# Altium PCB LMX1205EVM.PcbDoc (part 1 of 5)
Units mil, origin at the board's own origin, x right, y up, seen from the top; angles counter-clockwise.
Board outline 5000 x 5000 mil, 6 copper layers (Top Layer, RF GND, Signal Layer 3, Signal Layer 4, Signal Layer 5, Bottom Layer), stack 61.6 mil thick; 176 components, 99 nets, 572 pads, 2473 vias.
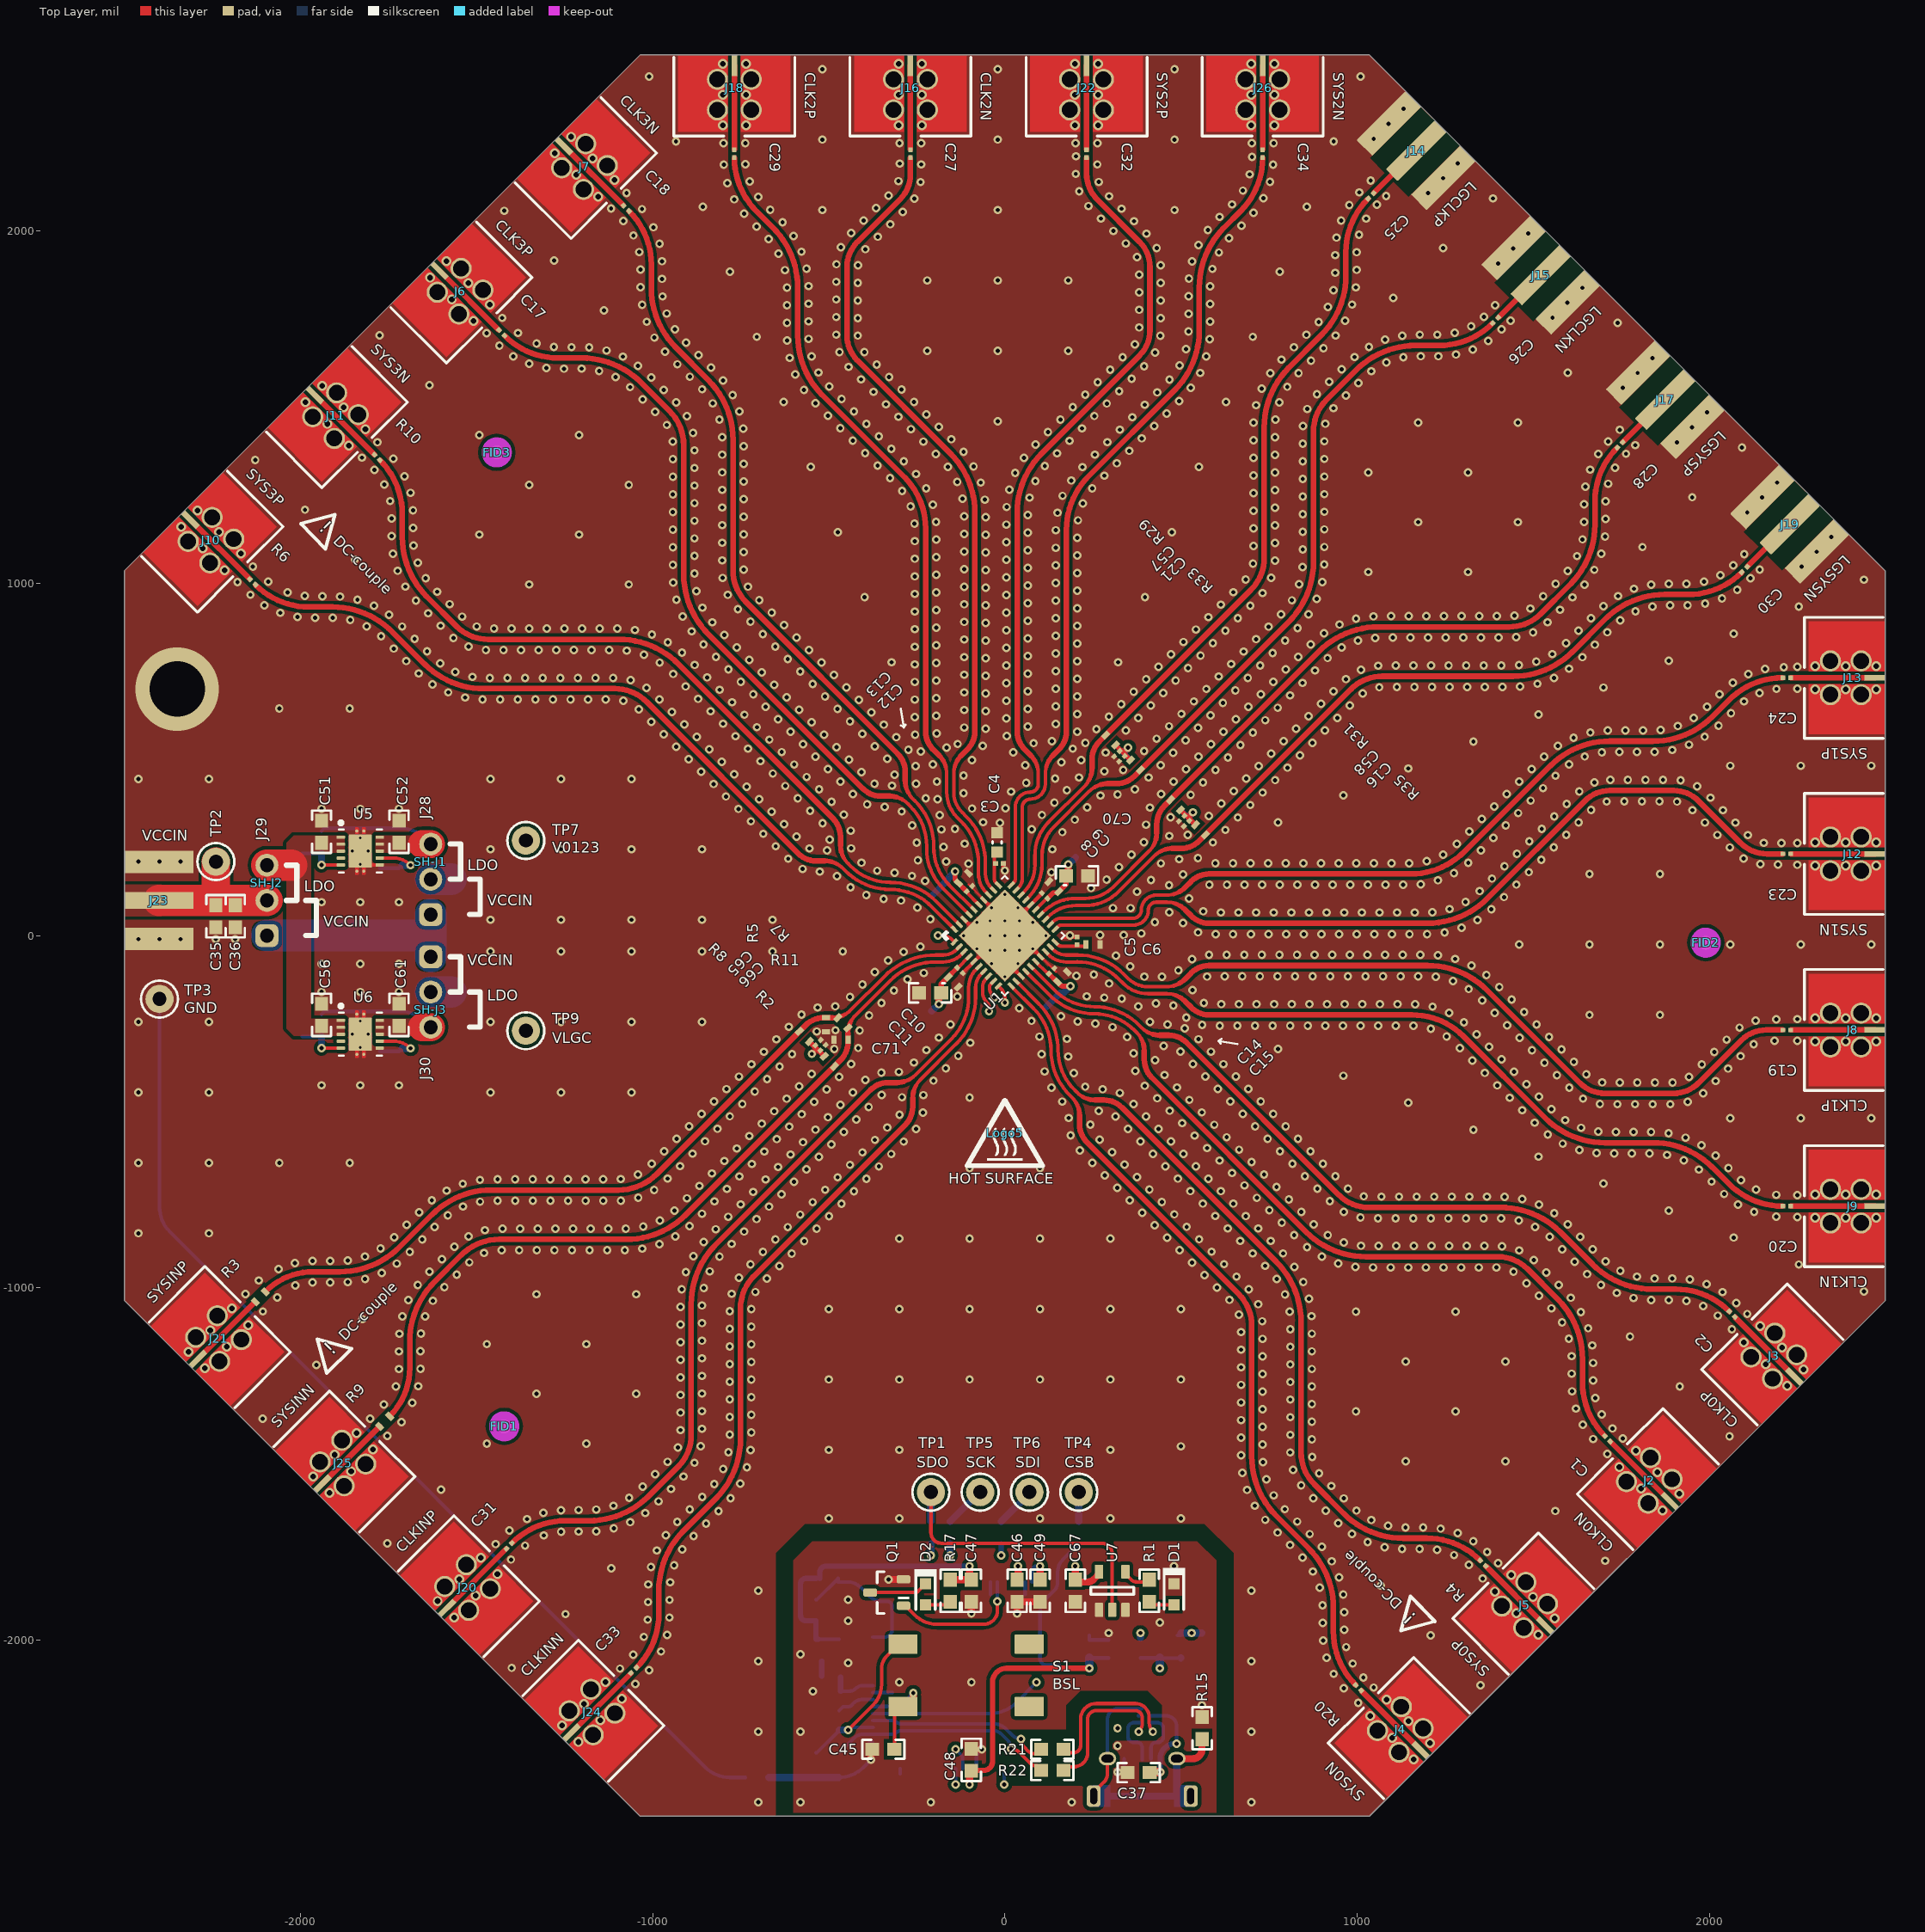
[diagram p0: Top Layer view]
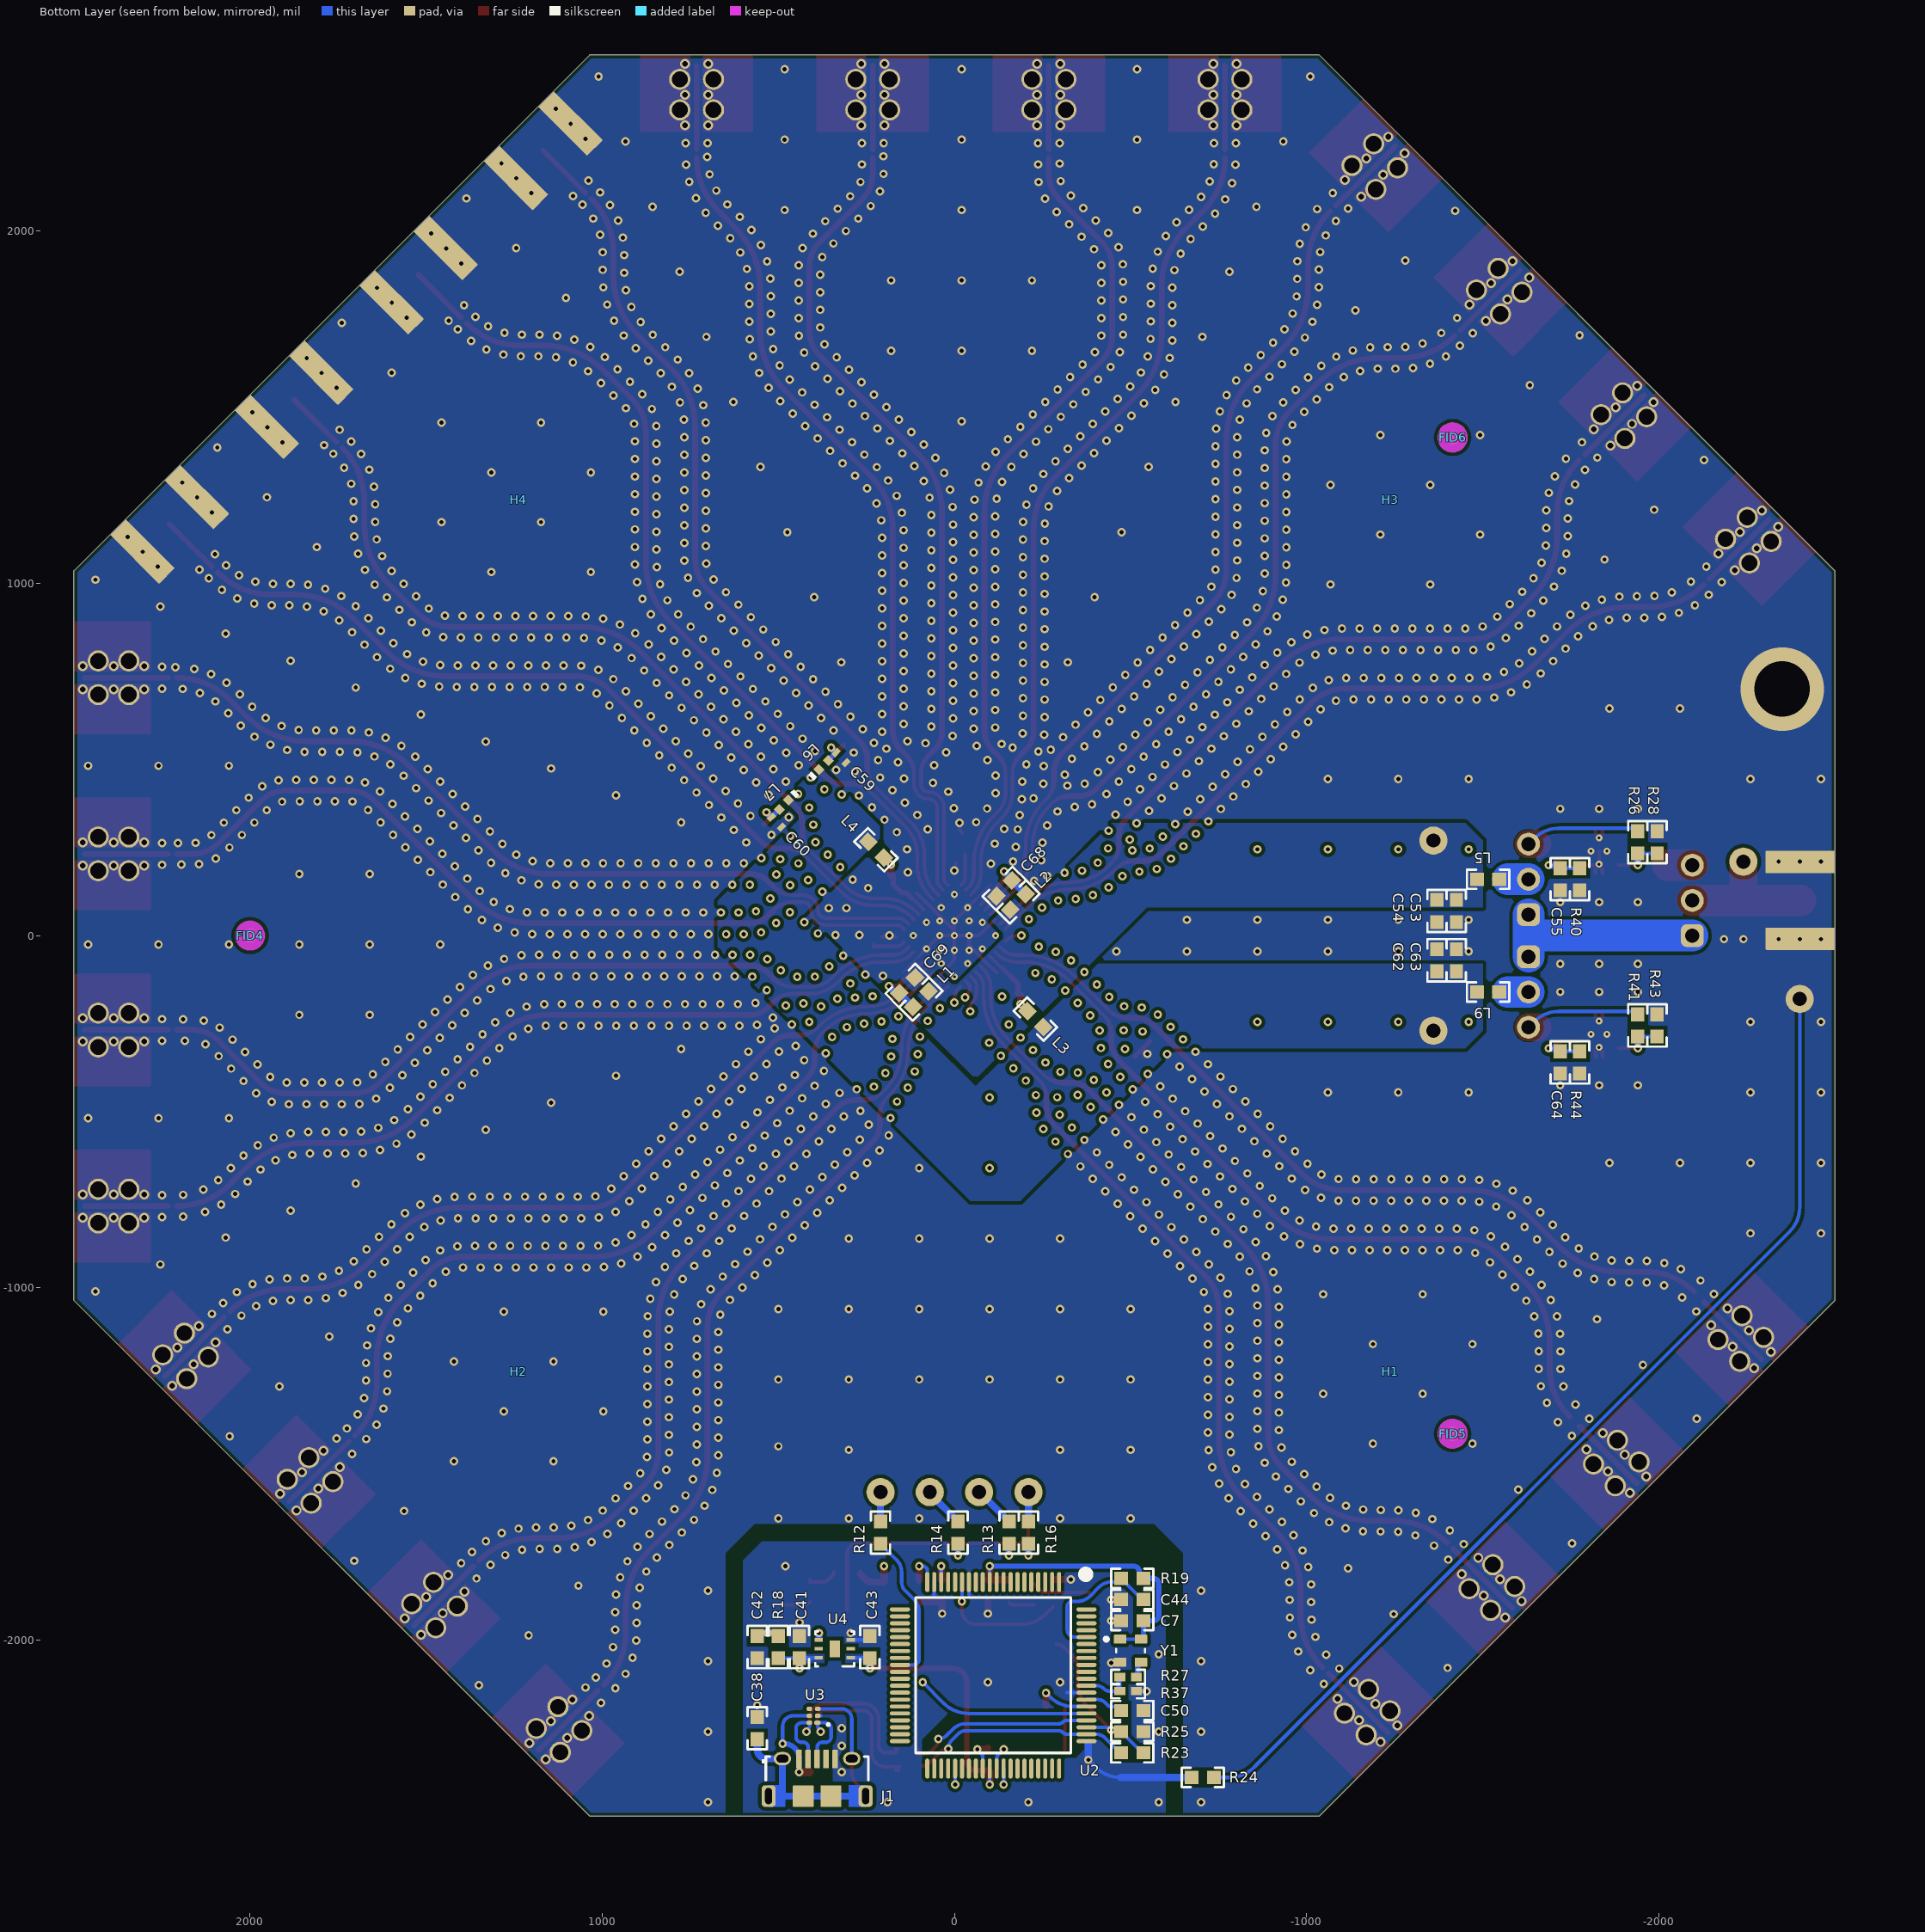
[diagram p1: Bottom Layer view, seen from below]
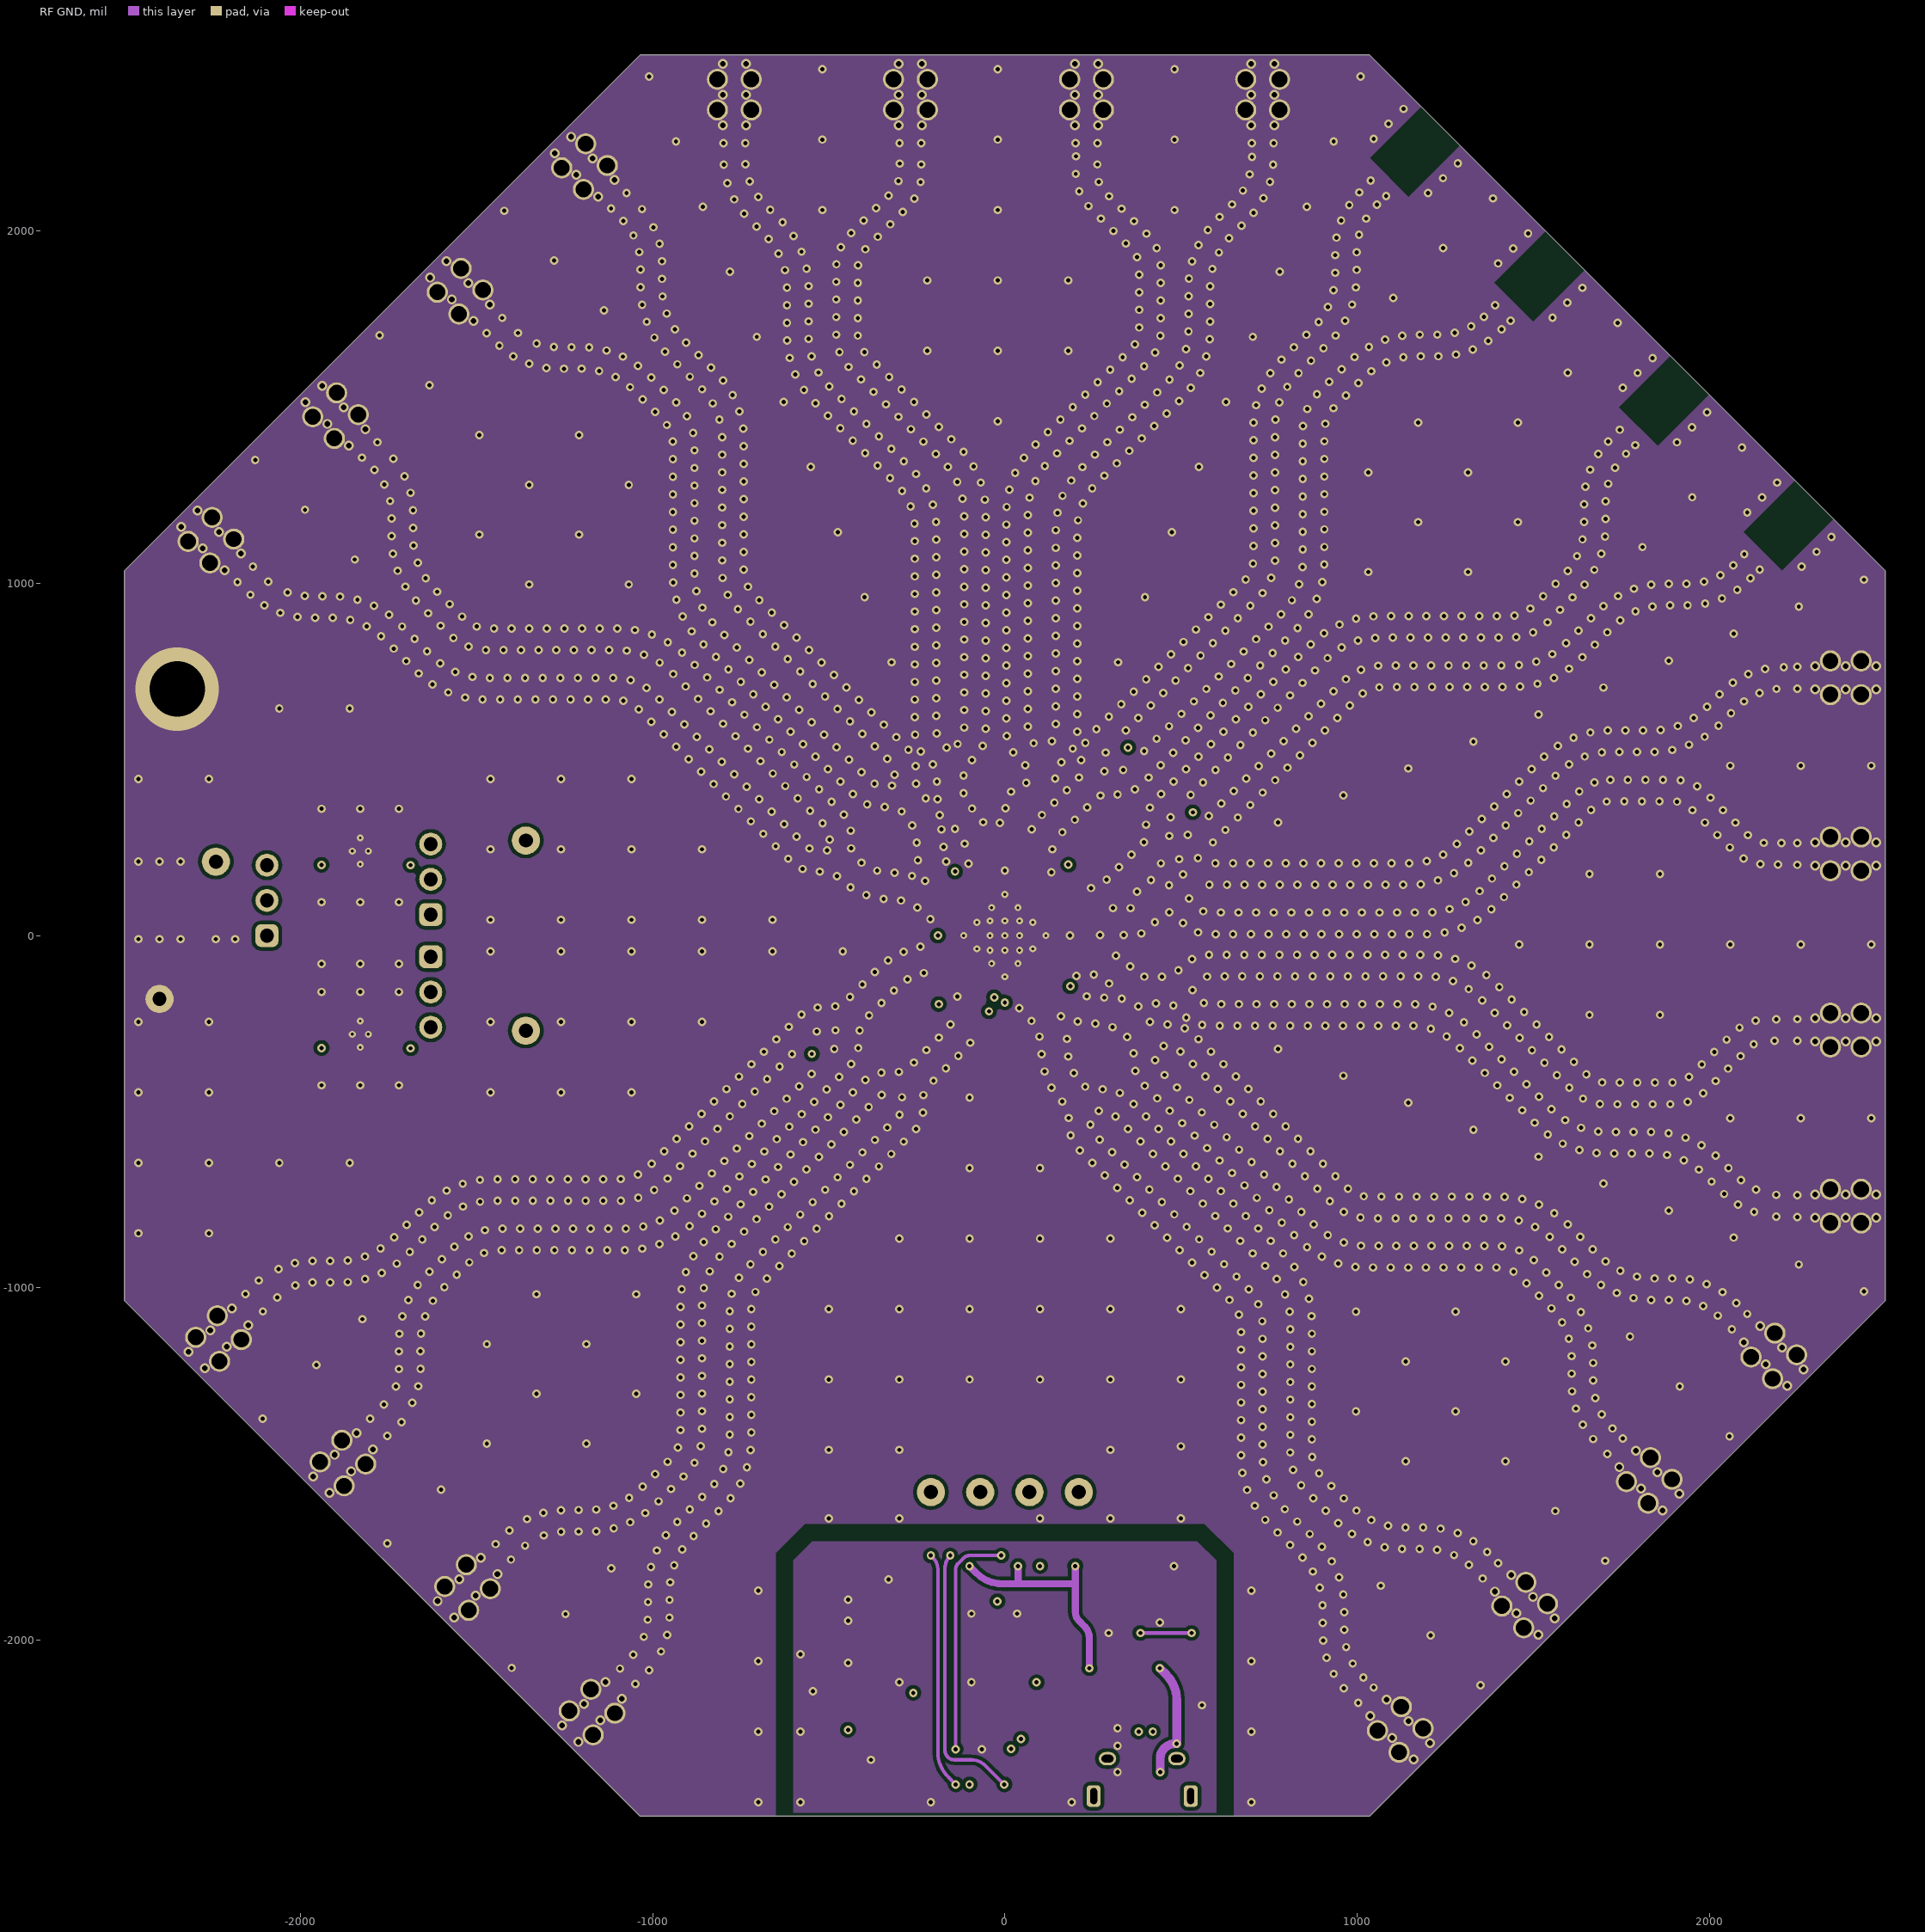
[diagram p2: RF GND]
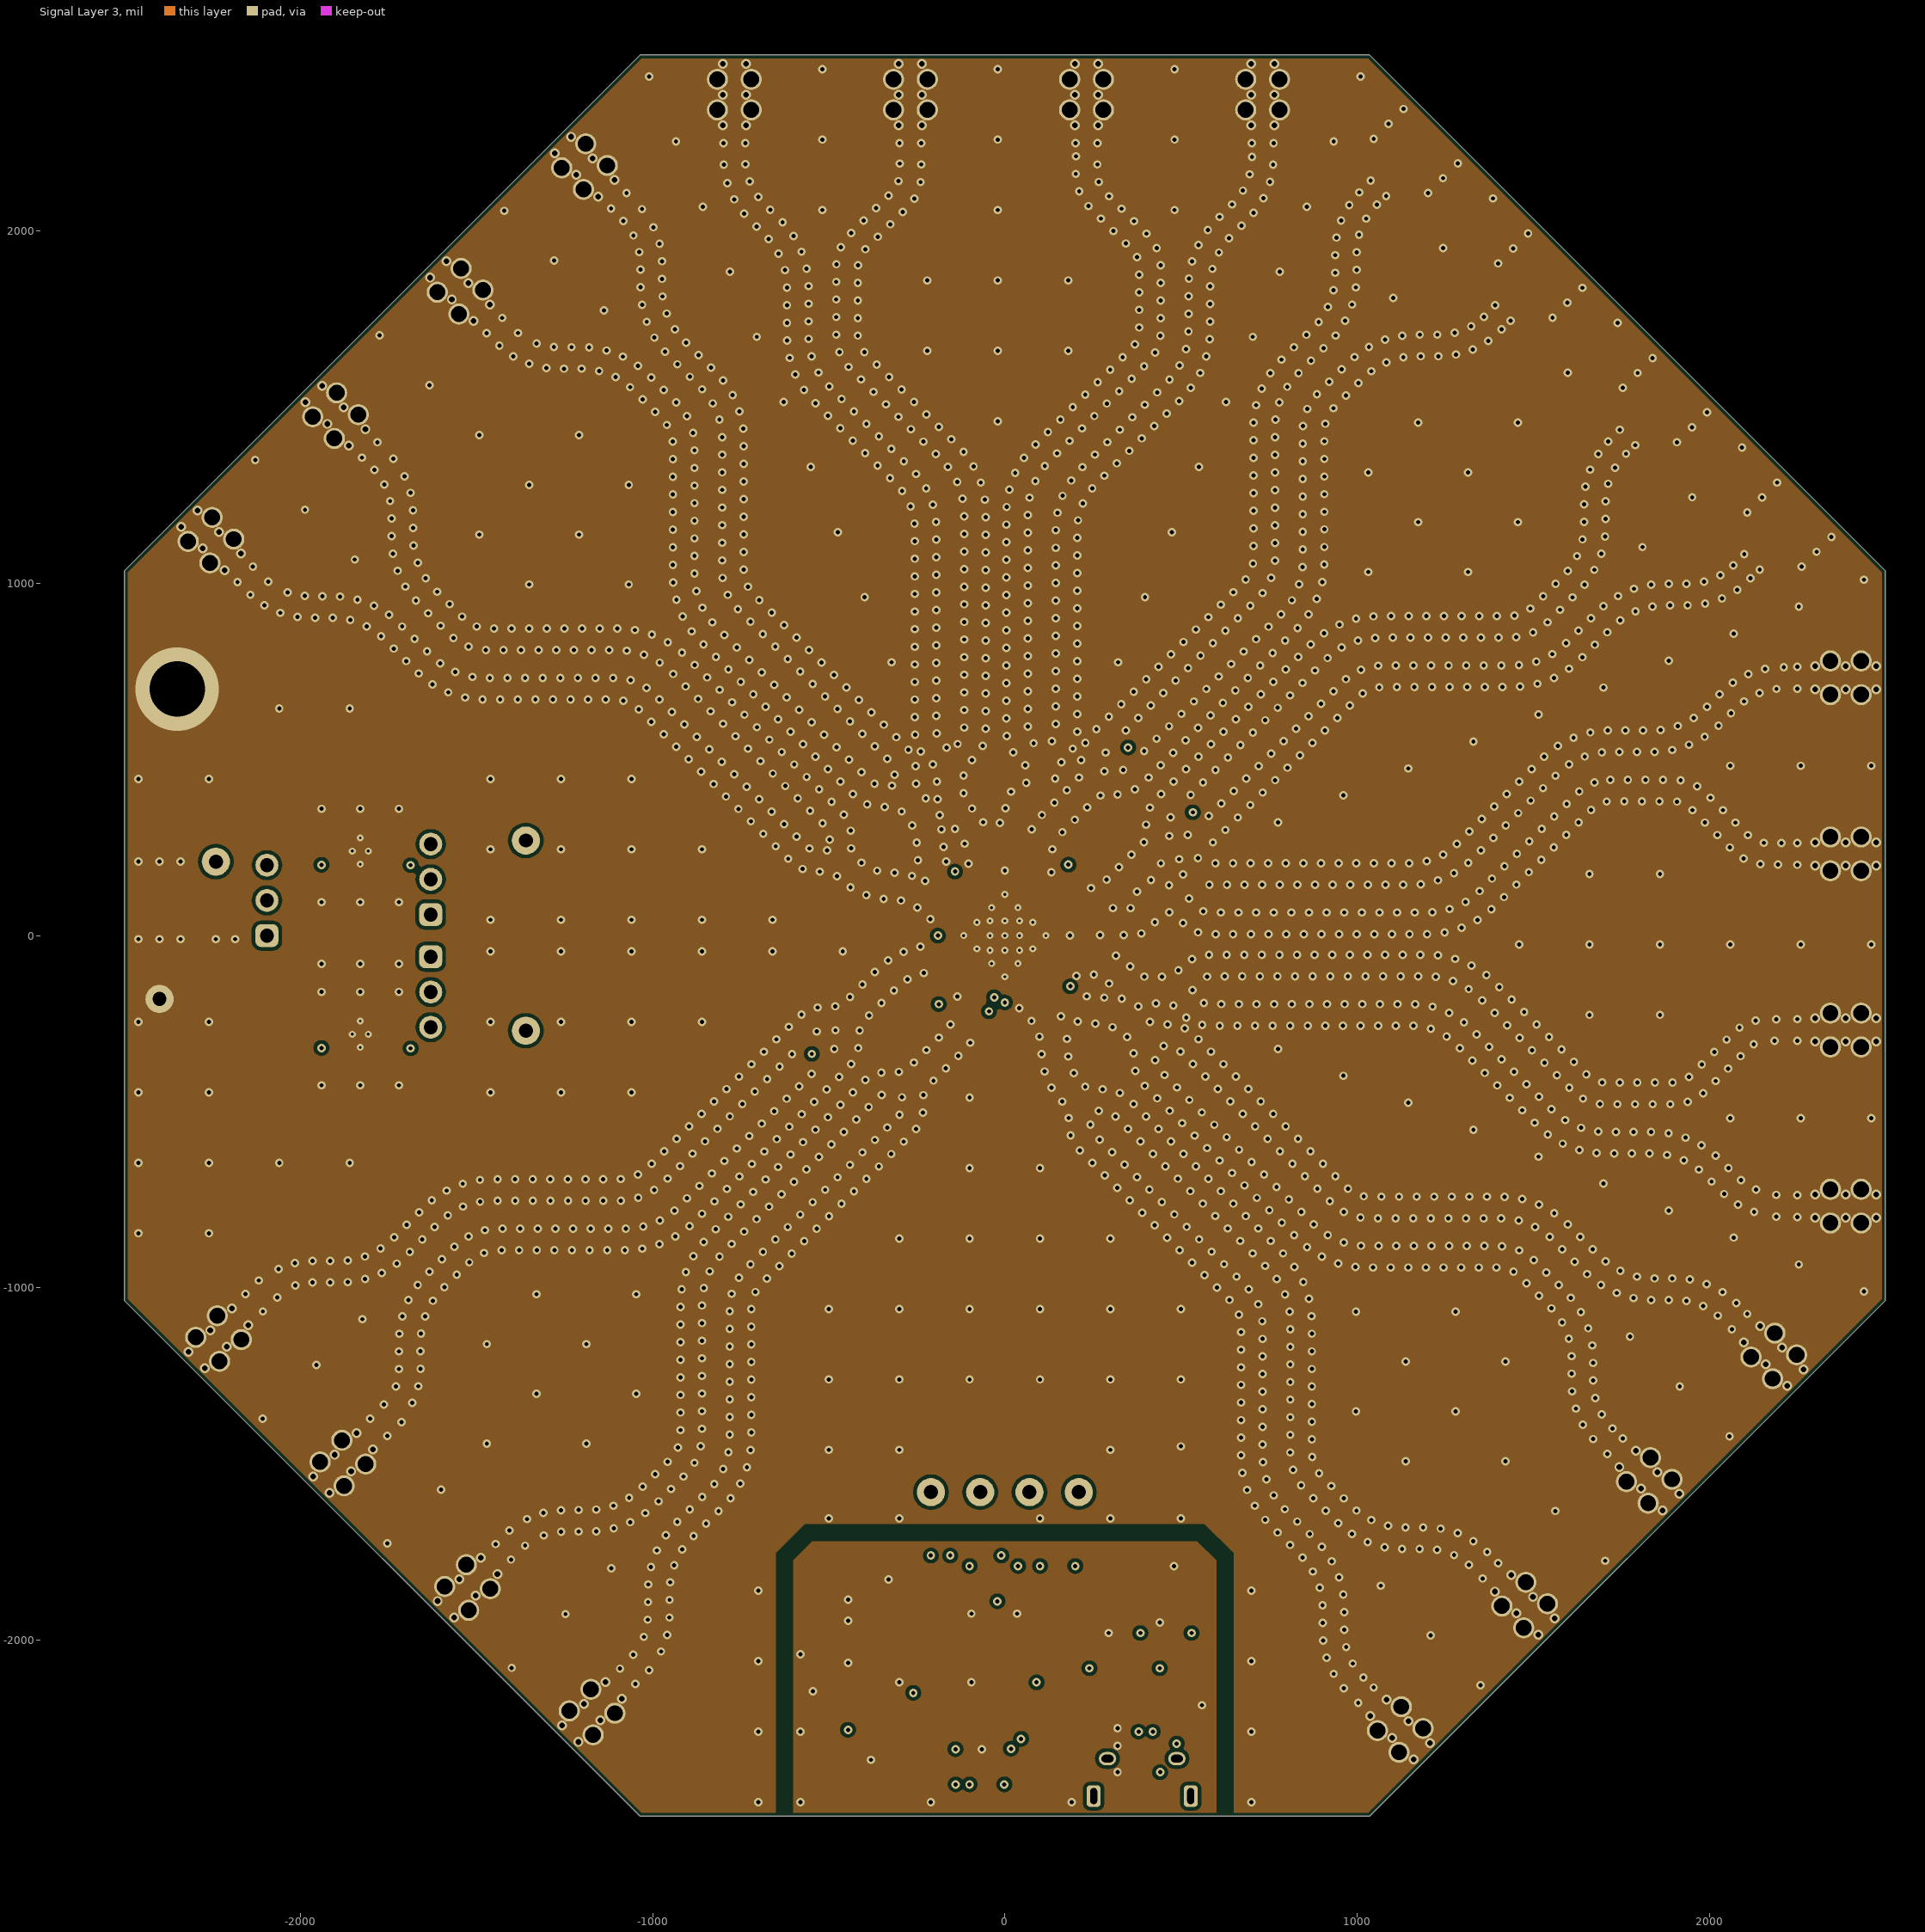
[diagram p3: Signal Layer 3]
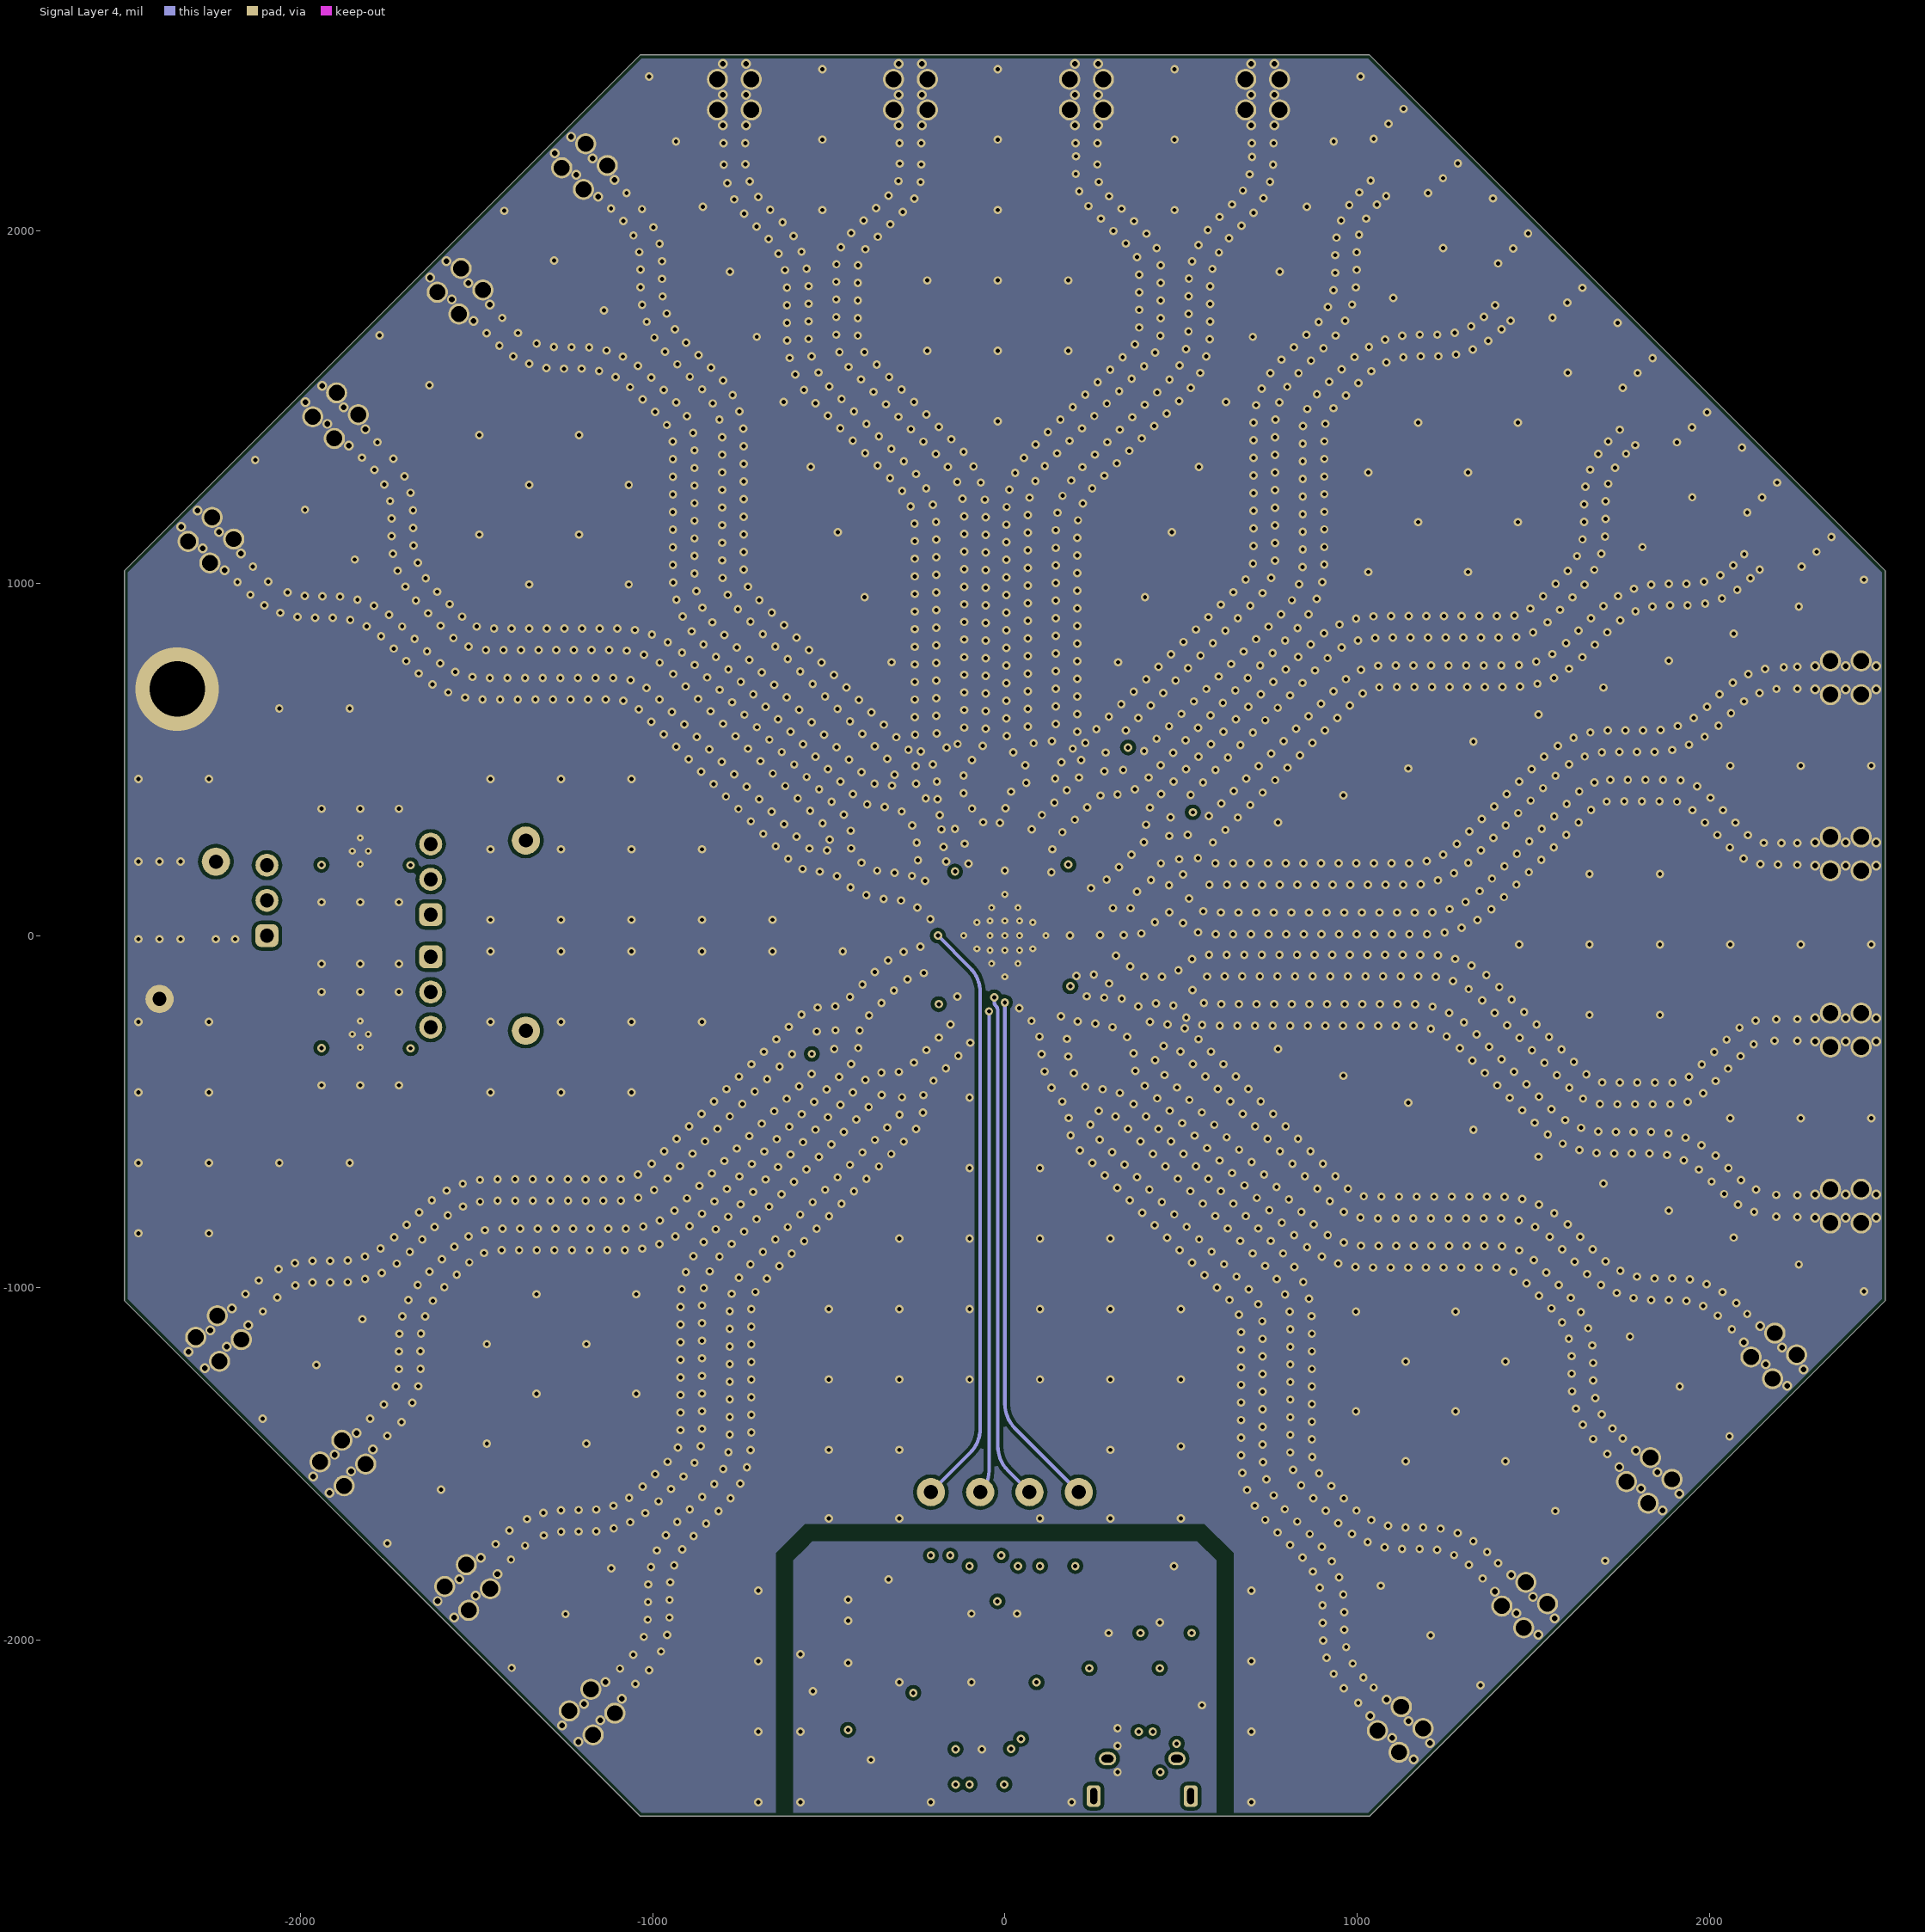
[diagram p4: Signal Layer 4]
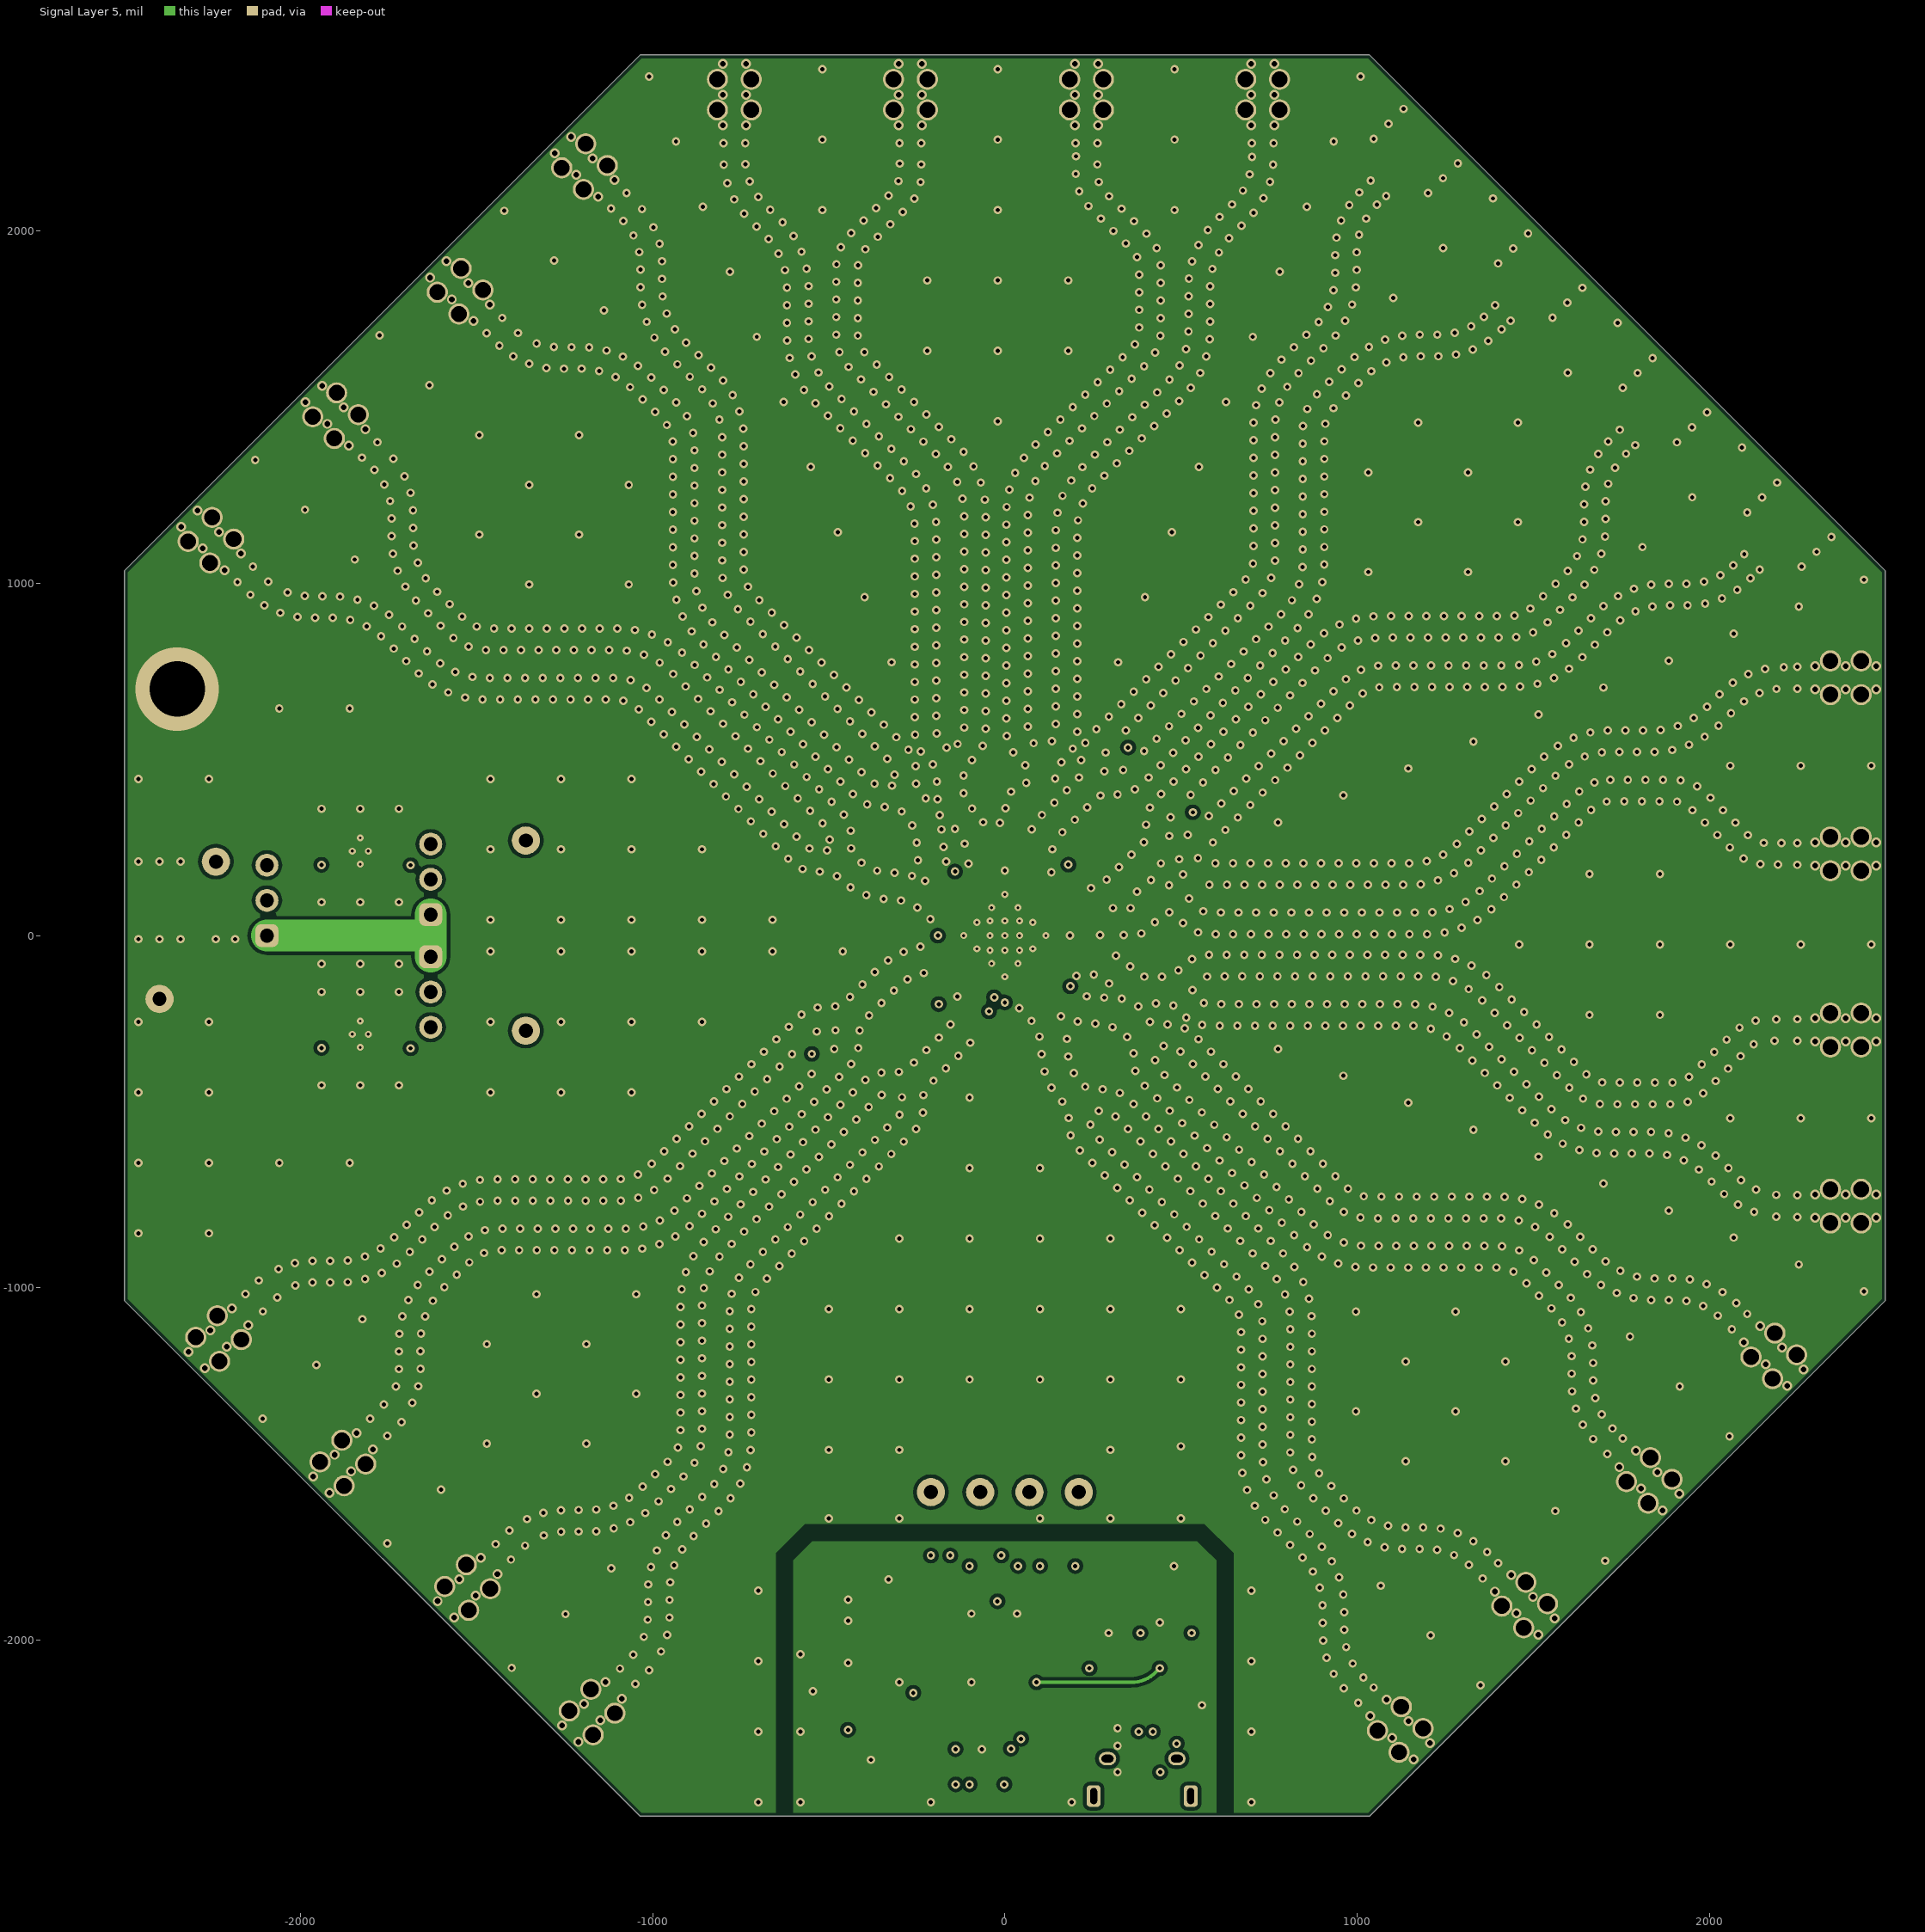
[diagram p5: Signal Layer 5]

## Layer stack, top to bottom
Top Solder: solder mask 0.4, Solder Resist, Dk 3.5
Top Layer: signal copper 2.8
Dielectric1: prepreg 8, RO4350B, Dk 3.48
RF GND: signal copper 1.4
Dielectric 2: prepreg 11, FR-4 High Tg, Dk 4.2
Signal Layer 3: signal copper 1.4
Dielectric 3: core 12.4, FR-4 High Tg, Dk 4.2
Signal Layer 4: signal copper 1.4
Dielectric 4: prepreg 11, FR-4 High Tg, Dk 4.2
Signal Layer 5: signal copper 1.4
Dielectric 5: prepreg 8, FR-4 High Tg, Dk 4.2
Bottom Layer: signal copper 2.8
Bottom Solder: solder mask 0.4, Solder Resist, Dk 3.5

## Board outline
-1035.53,-2500 -2500,-1035.53 -2500,1035.53 -1035.53,2500 1035.53,2500 2500,1035.53 2500,-1035.53 1035.53,-2500

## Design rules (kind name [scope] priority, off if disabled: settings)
AcuteAngle [All] p1: minimum=4.50000000000000E+0001 checktracksonly=FALSE
AssemblyTestPointUsage [All] p1: valid=2
BoardOutlineClearance BoardOutlineClearance_MountingHoles [OnCopper and InComponentClass('Mounting Holes')] p1: gap=10 ignorepadtopadclearanceinfootprint=FALSE
BoardOutlineClearance BoardOutlineClearance_Poly [OnCopper and IsPoly and not OnTopLayer and not OnLayer('RF GND')] p2: gap=10 ignorepadtopadclearanceinfootprint=FALSE
BoardOutlineClearance [OnCopper and Not InComponentClass('Logo') and not InComponentClass('FiducialMark') and not InRegion(1000,500,4000,800) and not InPoly and not InComponent('J1')and not InComponent('J2')and not InComponent('J3')and not InComponent('J4')and not InComponent('J5')and not InComponent('J6')and not InComponent('J7')and not InComponent('J8')and not InComponent('J9')and not InComponent('J10')and not InComponent('J11')and not InComponent('J12')and not InComponent('J13')and not InComponent('J14')and not InComponent('J15')and not InComponent('J16')and not InComponent('J17')and not InComponent('J18')and not InComponent('J19')and not InComponent('J20')and not InComponent('J21')and not InComponent('J22')and not InComponent('J23')and not InComponent('J24')and not InComponent('J25')and not InComponent('J26')and not InNet('GND')and not InNet('NetC35_1')] p3: gap=10 ignorepadtopadclearanceinfootprint=FALSE
Clearance Clearance_Keepouts [((IsTrack or IsArc) and not InPoly) and IsFree and IsKeepOut vs ((IsTrack or IsArc) and not InPoly) and IsFree and IsKeepOut] p1: gap=0 ignorepadtopadclearanceinfootprint=FALSE
Clearance IMPEDANCE [InPolygon vs InNetClass('50OHM_IMPED')] p2 off: gap=7.87 ignorepadtopadclearanceinfootprint=TRUE except(9.64: Arc-Fill Arc-Poly Arc-Region Track-Fill Track-Poly Track-Region)
Clearance Clearance_Poly [InPolygon] p3: gap=10 ignorepadtopadclearanceinfootprint=TRUE except(9.64: Arc-Fill Arc-Poly Arc-Region Track-Fill Track-Poly Track-Region)
Clearance Clearance_FiducialMark [IsKeepOut and InComponentClass('FiducialMark') vs IsPad and InComponentClass('FiducialMark')] p4: gap=0 ignorepadtopadclearanceinfootprint=TRUE
Clearance [All] p5: gap=7.87 ignorepadtopadclearanceinfootprint=TRUE
ComponentClearance ComponentClearance_MountingHoles_FiducialMarks [InComponentClass('Mounting Holes') vs InComponentClass('FiducialMark')] p1: gap=50 collisioncheckmode=3 verticalgap=10 showdistances=FALSE
ComponentClearance ComponentClearance_Shunt [InComponentClass('Header') vs InComponentClass('Shunt')] p2: gap=0 collisioncheckmode=3 verticalgap=0 showdistances=FALSE
ComponentClearance ComponentClearance_Logo [InComponentClass('Logo')] p3: gap=50 collisioncheckmode=3 verticalgap=10 showdistances=FALSE
ComponentClearance ComponentClearance_ScrewToNut [(HasFootprint('NY PMS 440 0025 PH')) vs (HasFootprint('Keystone_1902C'))] p4: gap=5 collisioncheckmode=3 verticalgap=10 showdistances=FALSE
ComponentClearance ComponentClearance_MountingHoles [InComponentClass('Mounting Holes')] p5: gap=250 collisioncheckmode=3 verticalgap=100000 showdistances=FALSE
ComponentClearance ComponentClearance_SmallPassives [HasFootprint('0201*') or HasFootprint('0402*') or HasFootprint('0508') or HasFootprint('0603*') or HasFootprint('0612') or HasFootprint('0805*') or HasFootprint('0815*') or HasFootprint('0830*') or HasFootprint('1206*') or HasFootprint('1210*') or HasFootprint('1808*') or HasFootprint('1812*') or HasFootprint('1825*') or HasFootprint('2010*') or HasFootprint('2220*') or HasFootprint('2225*') or HasFootprint('2512*') or HasFootprint('2728*') or HasFootprint('3518*') vs HasFootprint('0201*') or HasFootprint('0402*') or HasFootprint('0508') or HasFootprint('0603*') or HasFootprint('0612') or HasFootprint('0805*') or HasFootprint('0815*') or HasFootprint('0830*') or HasFootprint('1206*') or HasFootprint('1210*') or HasFootprint('1808*') or HasFootprint('1812*') or HasFootprint('1825*') or HasFootprint('2010*') or HasFootprint('2220*') or HasFootprint('2225*') or HasFootprint('2512*') or HasFootprint('2728*') or HasFootprint('3518*')] p6: gap=14.96 collisioncheckmode=3 verticalgap=10 showdistances=FALSE
ComponentClearance ComponentClearance_THtoSMT [IsThruComponent vs IsSMTComponent] p7: gap=40 collisioncheckmode=3 verticalgap=30 showdistances=FALSE
ComponentClearance ComponentClearance_THtoTH [IsThruComponent vs IsThruComponent] p8: gap=30 collisioncheckmode=3 verticalgap=30 showdistances=FALSE
ComponentClearance [All] p9: gap=30 collisioncheckmode=3 verticalgap=10 showdistances=FALSE
DiffPairsRouting [All] p1: maxlimit=100 minlimit=10 mostfreqgap=10 toplayer_minwidth=15 toplayer_maxwidth=15 toplayer_prefwidth=15 midlayer1_minwidth=15 midlayer1_maxwidth=15 midlayer1_prefwidth=15 midlayer2_minwidth=15 midlayer2_maxwidth=15 midlayer2_prefwidth=15 midlayer3_minwidth=15 midlayer3_maxwidth=15 midlayer3_prefwidth=15 midlayer4_minwidth=15 midlayer4_maxwidth=15 midlayer4_prefwidth=15 bottomlayer_minwidth=15 bottomlayer_maxwidth=15 bottomlayer_prefwidth=15 maxuncoupledlength=1000
FabricationTestPointUsage TestPointUsage [All] p1: valid=2 allowmultiple=FALSE
FabricationTestpoint Testpoint [All] p1: side=3 testpointundercomponent=TRUE minsize=40 maxsize=100 preferedsize=60 minholesize=0 maxholesize=40 preferedholesize=32 testpointgrid=1 allowsidetop=TRUE allowsidebottom=TRUE usegrid=TRUE gridtolerance=0.01
FanoutControl Fanout_LCC [IsLCC] p1: bgadir=Out bgaviamode=Centered fanoutstyle=Auto fanoutdirection=Alternating viagrid=1 // Fanout_LCC (Default Rule)
FanoutControl Fanout_BGA [IsBGA] p2: bgadir=Out bgaviamode=Centered fanoutstyle=Auto fanoutdirection=Alternating viagrid=1 // Fanout_BGA (Default Rule)
FanoutControl Fanout_Default [All] p4: bgadir=Out bgaviamode=Centered fanoutstyle=Auto fanoutdirection=Alternating viagrid=1 // Fanout_Default (Default Rule)
FanoutControl Fanout_Small [(CompPinCount < 5)] p5: bgadir=Out bgaviamode=Centered fanoutstyle=Auto fanoutdirection=OutThenIn viagrid=1 // Fanout_Small (Default Rule)
HoleSize [All] p1: absolutevalues=TRUE maxlimit=251 minlimit=7.87 maxpercent=80.000 minpercent=20.000
MinimumAnnularRing MinimumAnnularRing_ThermalPadVias [IsVia and InAnyComponent] p1: minimumring=5.91
MinimumAnnularRing [All] p2: minimumring=3
MinimumSolderMaskSliver MinimumSolderMaskSliver_Logo [InComponentClass('Logo') vs InComponentClass('Logo')] p1: minsoldermaskwidth=0.7
MinimumSolderMaskSliver [All] p2: minsoldermaskwidth=3.9
PlaneConnect [All] p1: planeconnectstyle=Relief reliefexpansion=10 reliefentries=4 reliefconductorwidth=10 reliefairgap=10
PolygonConnect [All] p1: connectstyle=Direct reliefconductorwidth=10 reliefentries=4 polygonreliefangle="90 Angle" airgapwidth=10
RoutingVias ThermalPadVias [IsVia and InAnyComponent] p1: holewidth=7.87 width=19.68 viastyle="Through Hole" minholewidth=7.87 minwidth=18 maxholewidth=16 maxwidth=28
RoutingVias AdditionalThermalVias [InNet('GND')] p2: holewidth=7.87 width=19.68 viastyle="Through Hole" minholewidth=7.87 minwidth=18 maxholewidth=160 maxwidth=240
RoutingVias [All] p3: holewidth=12 width=24 viastyle="Through Hole" minholewidth=12 minwidth=24 maxholewidth=160 maxwidth=240
SilkToBoardRegionClearance [Not ((IsComment or IsDesignator) And (Hide <> 'False')) and not InRegion(1000,500,4000,800)] p1:
SilkToSilkClearance SilkToSilkClearance_Pb-FreeLogo [(HasFootprint('Pb-Free_Overlay_Medium') OR HasFootprint('Pb-Free_Overlay_Small')) vs (HasFootprint('Pb-Free_Overlay_Medium') OR HasFootprint('Pb-Free_Overlay_Small'))] p1: silktosilkclearance=0
SilkToSilkClearance [All] p2: silktosilkclearance=3.94
SilkToSolderMaskClearance SilkToComponentPadClearance [(IsPad or IsFill or IsRegion) and InAnycomponent] p1: minsilkscreentomaskgap=5 clearancetoexposedcopper=TRUE
SilkToSolderMaskClearance "Silk to Solder Mask Opening" [All] p2: minsilkscreentomaskgap=3.94 clearancetoexposedcopper=FALSE
SolderMaskExpansion [All] p1: expansion=1.97
UnRoutedNet [All] p1: checkbadconnections=TRUE
Width [All] p1: maxlimit=100 minlimit=6 preferedwidth=10 checkconnectedcopper=TRUE
14 further rules are at their usual default settings.

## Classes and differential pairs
component class Shunt: SH-J1 SH-J2 SH-J3
net class 50OHM_IMPED: C2N C2P LGCN LGCP LGSN LGSP NetC1_1 NetC1_2 NetC2_1 NetC2_2 NetC17_1 NetC17_2 NetC18_1 NetC18_2 NetC19_1 NetC19_2 NetC20_1 NetC20_2 NetC23_1 NetC23_2 NetC24_1 NetC24_2 NetC25_1 NetC26_1 NetC27_1 NetC28_1 NetC29_1 NetC30_1 NetC31_1 NetC31_2 NetC32_1 NetC33_1 NetC33_2 NetC34_1 NetJ4_1 NetJ5_1 NetJ10_1 NetJ11_1 NetJ21_1 NetJ25_1 NetR2_1 NetR3_2 NetR4_2 NetR6_1 NetR10_1 NetR20_2 S2N S2P
component class LMX1205EVM_USB2ANY: C7 C37 C38 C41 C42 C43 C44 C45 C46 C47 C48 C49 C50 C67 D1 D2 J1 Q1 R1 R12 R13 R14 R15 R16 R17 R18 R19 R21 R22 R23 R24 R25 R27 R37 S1 TP1 TP4 TP5 TP6 U2 U3 U4 U7 Y1
component class LMX1205EVM_PWR: C35 C36 C51 C52 C53 C54 C55 C56 C61 C62 C63 C64 J23 J28 J29 J30 L5 L9 R26 R28 R40 R41 R43 R44 SH-J1 SH-J2 SH-J3 TP2 TP3 TP7 TP9 U5 U6
component class LMX1205EVM_BUF: C1 C2 C3 C4 C5 C6 C8 C9 C10 C11 C12 C13 C14 C15 C16 C17 C18 C19 C20 C21 C23 C24 C25 C26 C27 C28 C29 C30 C31 C32 C33 C34 C57 C58 C59 C60 C65 C66 C68 C69 C70 C71 J2 J3 J4 J5 J6 J7 J8 J9 J10 J11 J12 J13 J14 J15 J16 J17 J18 J19 J20 J21 J22 J24 J25 J26 L1 L2 L3 L4 L6 L7 R2 R3 R4 R5 R6 R7 R8 R9 R10 R11 R20 R29 R31 R33 R35 U1
component class Header: J28 J29 J30
component class LMX1205EVM_Hardware: FID1 FID2 FID3 FID4 FID5 FID6 H1 H2 H3 H4 Logo5
component class FiducialMark: FID1 FID2 FID3 FID4 FID5 FID6

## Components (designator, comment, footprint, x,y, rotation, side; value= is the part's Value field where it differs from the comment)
C1 "ATC530Z104KT10T" 0201_033L 1711.2,-1428.36 r135 top value=0.1uF
C2 "ATC530Z104KT10T" 0201_033L 2064.75,-1074.8 r135 top value=0.1uF
C3 "ATC530Z104KT10T" 0201_033L -15,205 r0 top value=0.1uF
C4 "GRM188R61A106KAALD" 0603L -22,265 r90 top value=10uF
C5 "550Z103PTT" 0201_033L 205,-15 r90 top value=0.01uF
C6 "GRM155R61E105KA12D" 0402S 250,-25 r0 top value=1uF
C7 "885012206046" 0603 -505,-1945 r0 bottom value=0.1uF
C8 "ATC530Z104KT10T" 0201_033L 113.14,113.14 r135 top value=0.1uF
C9 "GRM155R61E105KA12D" 0402S 139.3,139.3 r135 top value=1uF
C10 "ATC530Z104KT10T" 0201_033L -127.28,-98.99 r315 top value=0.1uF
C11 "GRM155R61E105KA12D" 0402S -146.72,-131.88 r315 top value=1uF
C12 "ATC530Z104KT10T" 0201_033L -100.41,132.94 r45 top value=0.1uF
C13 "GRM155R61E105KA12D" 0402S -117.73,163.7 r45 top value=1uF
C14 "ATC530Z104KT10T" 0201_033L 132.94,-100.41 r45 top value=0.1uF
C15 "GRM155R61E105KA12D" 0402S 163.7,-117.73 r45 top value=1uF
C16 "ATC530Z104KT10T" 0201_033L 516.19,318.2 r45 top value=0.1uF
C17 "ATC530Z104KT10T" 0201_033L -1428.36,1711.2 r135 top value=0.1uF
C18 "ATC530Z104KT10T" 0201_033L -1074.8,2064.75 r135 top value=0.1uF
C19 "ATC530Z104KT10T" 0201_033L 2220,-268 r180 top value=0.1uF
C20 "ATC530Z104KT10T" 0201_033L 2220,-768 r180 top value=0.1uF
C21 "ATC530Z104KT10T" 0201_033L 332.34,502.05 r45 top value=0.1uF
C23 "ATC530Z104KT10T" 0201_033L 2220,232 r180 top value=0.1uF
C24 "ATC530Z104KT10T" 0201_033L 2220,732 r180 top value=0.1uF
C25 "ATC530Z104KT10T" 0201_033L 1039.45,2100.11 r225 top value=0.1uF
C26 "ATC530Z104KT10T" 0201_033L 1393,1746.55 r225 top value=0.1uF
C27 "ATC530Z104KT10T" 0201_033L -268,2220 r270 top value=0.1uF
C28 "ATC530Z104KT10T" 0201_033L 1746.55,1393 r225 top value=0.1uF
C29 "ATC530Z104KT10T" 0201_033L -768,2220 r270 top value=0.1uF
C30 "ATC530Z104KT10T" 0201_033L 2100.11,1039.45 r225 top value=0.1uF
C31 "ATC530Z104KT10T" 0201_033L -1407.14,-1732.41 r45 top value=0.1uF
C32 "ATC530Z104KT10T" 0201_033L 232,2220 r270 top value=0.1uF
C33 "ATC530Z104KT10T" 0201_033L -1053.59,-2085.96 r45 top value=0.1uF
C34 "ATC530Z104KT10T" 0201_033L 732,2220 r270 top value=0.1uF
C35 "885012206052" 0603 -2240,55 r270 top value=1uF
C36 "885012206046" 0603 -2185,55 r270 top value=0.1uF
C37 "885012106018" 0603 380,-2376 r180 top value=2.2uF
C38 "885012206086" 0603 560,-2250 r90 bottom value=3300pF
C41 "885012206052" 0603 440,-2020 r90 bottom value=1uF
C42 "885012206046" 0603 560,-2020 r270 bottom value=0.1uF
C43 "885012206052" 0603 240,-2020 r90 bottom value=1uF
C44 "885012206036" 0603 -505,-1885 r0 bottom value=2200pF
C45 "C0603C221J5GACTU" 0603 -345,-2310 r180 top value=220pF
C46 "885012206046" 0603 35,-1860 r270 top value=0.1uF
C47 "885012206046" 0603 -95,-1860 r270 top value=0.1uF
C48 "885012206046" 0603 -95,-2340 r90 top value=0.1uF
C49 "GRM188R71C474KA88D" 0603 100,-1860 r270 top value=0.47uF
C50 "C0603C221J5GACTU" 0603 -505,-2200 r180 bottom value=220pF
C51 "GRM188R61A106KAALD" 0603 -1940,295 r90 top value=10uF
C52 "GRM188R61A106KAALD" 0603 -1720,295 r90 top value=10uF
C53 "GRM188R61A106KAALD" 0603 -1425,70 r90 bottom value=10uF
C54 "885012206046" 0603 -1370,70 r270 bottom value=0.1uF
C55 "GRM188Z71C475KE21D" 0603 -1720,160 r270 bottom value=4.7uF
C56 "GRM188R61A106KAALD" 0603 -1940,-225 r90 top value=10uF
C57 "ATC530Z104KT10T" 0201_033L 318.2,516.19 r45 top value=0.1uF
C58 "ATC530Z104KT10T" 0201_033L 502.05,332.34 r45 top value=0.1uF
C59 "GRM155R61E105KA12D" 0402S 321.73,505.58 r225 bottom value=1uF
C60 "GRM155R61E105KA12D" 0402S 505.58,321.73 r225 bottom value=1uF
C61 "GRM188R61A106KAALD" 0603 -1720,-225 r90 top value=10uF
C62 "GRM188R61A106KAALD" 0603 -1370,-70 r270 bottom value=10uF
C63 "885012206046" 0603 -1425,-70 r90 bottom value=0.1uF
C64 "GRM188Z71C475KE21D" 0603 -1720,-360 r270 bottom value=4.7uF
C65 "ATC530Z104KT10T" 0201_033L -530.33,-304.06 r225 top value=0.1uF
C66 "ATC530Z104KT10T" 0201_033L -516.19,-318.2 r225 top value=0.1uF
C67 "885012206046" 0603 200,-1860 r270 top value=0.1uF
C68 "GRM188R61A106KAALD" 0603 -141.42,134.35 r135 bottom value=10uF
C69 "GRM188R61A106KAALD" 0603 134.35,-141.42 r315 bottom value=10uF
C70 "GRM188R61A106KAALD" 0603 205.06,169.71 r180 top value=10uF
C71 "GRM188R61A106KAALD" 0603 -212.13,-162.63 r0 top value=10uF
D1 "LD" LED_LTST-C190 480,-1870 r90 top value=Green
D2 "USB" LED_LTST-C190 -225,-1870 r90 top value=Green
FID1 "Fiducial" Fiducial10-20 -1421.28,-1393 r0 top
FID2 "Fiducial" Fiducial10-20 1990,-20 r0 top
FID3 "Fiducial" Fiducial10-20 -1442.5,1371.79 r0 top
FID4 "Fiducial" Fiducial10-20 2000,0 r180 bottom
FID5 "Fiducial" Fiducial10-20 -1414.21,-1414.21 r225 bottom
FID6 "Fiducial" Fiducial10-20 -1414.21,1414.21 r180 bottom
H1 "SJ61A6" 3M_SJ61A6 -1237.44,-1237.44 r180 bottom
H2 "SJ61A6" 3M_SJ61A6 1237.44,-1237.44 r180 bottom
H3 "SJ61A6" 3M_SJ61A6 -1237.44,1237.44 r180 bottom
H4 "SJ61A6" 3M_SJ61A6 1237.44,1237.44 r180 bottom
J1 "10118194-0001LF" FCI_10118194-0001LF 390,-2500 r180 bottom
J2 "CLK0N" Johnson_142-0761-881 1829.64,-1546.8 r225 top
J3 "CLK0P" Johnson_142-0761-881 2183.19,-1193.24 r225 top
J4 "SYS0N" Johnson_142-0761-881 1122.53,-2253.9 r225 top
J5 "SYS0P" Johnson_142-0761-881 1476.09,-1900.35 r225 top
J6 "CLK3P" Johnson_142-0761-881 -1546.8,1829.64 r45 top
J7 "CLK3N" Johnson_142-0761-881 -1193.24,2183.19 r45 top
J8 "CLK1P" Johnson_142-0761-881 2387.5,-268 r270 top
J9 "CLK1N" Johnson_142-0761-881 2387.5,-768 r270 top
J10 "SYS3P" Johnson_142-0761-881 -2253.9,1122.53 r45 top
J11 "SYS3N" Johnson_142-0761-881 -1900.35,1476.09 r45 top
J12 "SYS1N" Johnson_142-0761-881 2387.5,232 r270 top
J13 "SYS1P" Johnson_142-0761-881 2387.5,732 r270 top
J14 "LGCLKP" FP-CON-SMA-EDGE-S_CONN_JACK-MFG 1370.02,2430.68 r315 top
J15 "LGCLKN" FP-CON-SMA-EDGE-S_CONN_JACK-MFG 1723.57,2077.13 r315 top
J16 "CLK2N" Johnson_142-0761-881 -268,2387.5 r0 top
J17 "LGSYSP" FP-CON-SMA-EDGE-S_CONN_JACK-MFG 2077.13,1723.57 r315 top
J18 "CLK2P" Johnson_142-0761-881 -768,2387.5 r0 top
J19 "LGSYSN" FP-CON-SMA-EDGE-S_CONN_JACK-MFG 2430.68,1370.02 r315 top
J20 "CLKINP" Johnson_142-0761-881 -1525.58,-1850.85 r135 top
J21 "SYSINP" Johnson_142-0761-881 -2232.69,-1143.75 r135 top
J22 "SYS2P" Johnson_142-0761-881 232,2387.5 r0 top
J23 "VCCIN" FP-CON-SMA-EDGE-S_CONN_JACK-MFG -2687.5,100 r90 top
J24 "CLKINN" Johnson_142-0761-881 -1172.03,-2204.41 r135 top
J25 "SYSINN" Johnson_142-0761-881 -1879.14,-1497.3 r135 top
J26 "SYS2N" Johnson_142-0761-881 732,2387.5 r0 top
J28 "TSW-103-07-G-S" TSW-103-07-G-S -1630,160 r90 top
J29 "TSW-103-07-G-S" TSW-103-07-G-S -2095,100 r90 top
J30 "TSW-103-07-G-S" TSW-103-07-G-S -1630,-160 r270 top
L1 "120Ω" 0603 95.46,-180.31 r315 bottom value="120 ohm"
L2 "120Ω" 0603 -180.31,95.46 r135 bottom value="120 ohm"
L3 "120Ω" 0603 -229.81,-236.88 r45 bottom value="120 ohm"
L4 "120Ω" 0603 222.74,243.95 r225 bottom value="120 ohm"
L5 "120Ω" 0603 -1515,160 r0 bottom value="120 ohm"
L6 "LQG15HS18NJ02D" IND_LQG15H 371.23,484.37 r135 bottom value=18nH
L7 "LQG15HS18NJ02D" IND_LQG15H 484.37,371.23 r315 bottom value=18nH
L9 "120Ω" 0603 -1515,-160 r0 bottom value="120 ohm"
Logo5 "HOT SURFACE" IEC_HotSurface_Small 0,-560 r0 top
Q1 "BSS138" SOT-23 -335,-1865 r180 top value=50V
R1 "CRCW0603330RJNEA" 0603 410,-1860 r90 top value=330
R2 "CRCW040210K0JNED" 0402S -498.51,-357.09 r135 top value=10k
R3 "CRCW04020000Z0ED" 0402S -2114.25,-1025.3 r45 top value=0
R4 "CRCW02010000Z0ED" 0201L 1357.65,-1781.91 r135 top value=0
R5 "CRCW040210K0JNED" 0402S -507.7,-253.14 r90 top value=10k
R6 "CRCW02010000Z0ED" 0201L -2135.46,1004.09 r135 top value=0
R7 "CRCW0402100RJNED" 0402S -459.62,-247.49 r135 top value=100
R8 "CRCW040210K0JNED" 0402S -569.22,-286.38 r315 top value=10k
R9 "CRCW04020000Z0ED" 0402S -1760.7,-1378.86 r45 top value=0
R10 "CRCW02010000Z0ED" 0201L -1781.91,1357.65 r135 top value=0
R11 "CRCW040210K0JNED" 0402S -465.28,-295.57 r0 top value=10k
R12 "CRCW0603200RFKEA" 0603 210,-1695 r90 bottom value=200
R13 "CRCW0603200RFKEA" 0603 -155,-1695 r90 bottom value=200
R14 "CRCW0603200RFKEA" 0603 -10,-1695 r90 bottom value=200
R15 "CRCW06031M00JNEA" 0603 560,-2250 r270 top value=1.0Meg
R16 "CRCW0603200RFKEA" 0603 -210,-1695 r90 bottom value=200
R17 "CRCW0603330RJNEA" 0603 -155,-1860 r90 top value=330
R18 "CRCW060310K0JNEA" 0603 500,-2020 r270 bottom value=10k
R19 "CRCW060333K0JNEA" 0603 -505,-1825 r180 bottom value=33k
R20 "CRCW02010000Z0ED" 0201L 1004.09,-2135.46 r135 top value=0
R21 "CRCW060333R0JNEA" 0603 135,-2310 r180 top value=33
R22 "CRCW060333R0JNEA" 0603 135,-2370 r180 top value=33
R23 "CRCW06031K50JNEA" 0603 -505,-2320 r0 bottom value=1.5k
R24 "CRCW06030000Z0EA" 0603 -705,-2390 r180 bottom value=0
R25 "CRCW06031M20JNEA" 0603 -505,-2260 r0 bottom value=1.2Meg
R26 "CRCW0603133KFKEA" 0603 -1940,265 r90 bottom value=133k
R27 "CRCW04021K78FKED" 0402 -493,-2105 r0 bottom value=1.78k
R28 "CRCW060312K4FKEA" 0603 -1995,265 r270 bottom value=12.4k
R29 "CRCW040249R9FKED" 0402S 300.52,555.08 r135 top value=49.9
R31 "CRCW040249R9FKED" 0402S 484.37,371.23 r135 top value=49.9
R33 "CRCW040249R9FKED" 0402S 371.23,484.37 r135 top value=49.9
R35 "CRCW040249R9FKED" 0402S 555.08,300.52 r135 top value=49.9
R37 "CRCW04021K00FKED" 0402 -493,-2145 r0 bottom value=1.00k
R40 "CRCW060316K5FKEA" 0603 -1775,160 r90 bottom value=16.5k
R41 "CRCW0603133KFKEA" 0603 -1940,-255 r90 bottom value=133k
R43 "CRCW060312K4FKEA" 0603 -1994.93,-255 r270 bottom value=12.4k
R44 "CRCW060316K5FKEA" 0603 -1775,-360 r90 bottom value=16.5k
S1 "BSL" SW_FSM4JSMA -110,-2100 r90 top
SH-J1 "SNT-100-BK-G" SNT-100-BK-G -1630,210 r270 top value=1x2
SH-J2 "SNT-100-BK-G" SNT-100-BK-G -2095,150 r270 top value=1x2
SH-J3 "SNT-100-BK-G" SNT-100-BK-G -1630,-210 r270 top value=1x2
TP1 "SDO" Keystone5002 -210,-1580 r90 top
TP2 "VCCIN" Keystone5000 -2240,210 r0 top
TP3 "GND" Keystone5001 -2400,-180 r90 top
TP4 "CSB" Keystone5002 210,-1580 r90 top
TP5 "SCK" Keystone5002 -70,-1580 r90 top
TP6 "SDI" Keystone5002 70,-1580 r90 top
TP7 "V0123" Keystone5000 -1360,270 r90 top
TP9 "VLGC" Keystone5000 -1360,-270 r90 top
U1 "LMX1205" RHA0040C-MFG 0,0 r45 top
U2 "MSP430F5529IPN" PN0080A_N -110,-2100 r270 bottom
U3 "TPD4S009DRYR" DRY0006A 400,-2215 r0 bottom
U4 "LP5900SDX-3.3/NOPB" NGF0006A 340,-2025 r0 bottom
U5 "TPS7A9401DSC" DSC0010J-MFG -1830,240 r0 top
U6 "TPS7A9401DSC" DSC0010J-MFG -1830,-280 r0 top
U7 "SN74LVC1G17DBVR" DBV0005A_N 305,-1860 r90 top
Y1 "CDC6CXXXXXXXDLFT" DLF0004A-MFG -500,-2030 r180 bottom

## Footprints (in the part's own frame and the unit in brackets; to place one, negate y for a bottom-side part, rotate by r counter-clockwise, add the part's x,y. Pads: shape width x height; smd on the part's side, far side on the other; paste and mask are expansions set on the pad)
3M_SJ61A6 [mil] "BUMPER CYLIN 0.312\" DIA"
  body extent -156,-156 156,156, height 195
0201_033L [mm] "0201"
  rect 0.36x0.32 smd mask+0.048: 1(-0.28,0) 2(0.28,0)
  body extent -0.31,-0.16 0.31,0.16, height 0.33
0201L [mm] "Data from Kemet datasheet CC101_COM dated 7/28/11"
  rect 0.36x0.32 smd mask+0.048: 1(-0.28,0) 2(0.28,0)
  body extent -0.31,-0.16 0.31,0.16, height 0.26
0402 [mm] "0402 from SM-752 data"
  rect 0.8x0.6 smd: 1(-0.6,0) 2(0.6,0)
  silkscreen extent -1.22,-0.52 1.22,0.52, body extent -0.55,-0.3 0.55,0.3, height 0.6
0402S [mil] "Based on C0402S footprint from PADS legacy"
  rect 15x24 smd: 1(-20,0) 2(20,0)
  body extent -22,-12 22,12, height 24
0603 [mm] "0603 from SM-752 data"
  rect 1x0.95 smd: 1(-0.8,0) 2(0.8,0)
  silkscreen extent -1.52,-0.69 1.52,0.69, body extent -0.87,-0.47 0.87,0.47, height 1
0603L [mm] "0603 from SM-752 data"
  rect 0.8x0.85 smd: 1(-0.7,0) 2(0.7,0)
  silkscreen extent -0.07,-0.33 0.07,0.32, body extent -0.87,-0.47 0.87,0.47, height 1
DBV0005A_N [mm] "SOT23, 5-Leads, Body 2.9x1.6mm, Pitch 0.95mm, Lead Span 2.8mm, IPC Medium Density"
  rrect17% 1x0.6 smd: 1(-1.375,0.95) 2(-1.375,0) 3(-1.375,-0.95) 4(1.375,-0.95) 5(1.375,0.95)
  silkscreen extent -0.25,-1.55 0.25,1.55, body extent -1.42,-1.46 1.42,1.46, height 1.09
DLF0004A-MFG [mm]
  rrect15% 0.9x0.65 smd paste-1000 mask+0: 1(-0.75,0.825) 2(-0.75,-0.825) 3(0.75,-0.825) 4(0.75,0.825)
  silkscreen extent -1.88,-0.13 1.05,0.95, body extent -1,-1.25 1,1.25, height 1
DRY0006A [mm] "USON-6"
  rrect67% 0.45x0.3 smd paste-0.05 mask-0.05: 1(-0.275,0.5)
  rrect67% 0.4x0.3 smd paste-0.05 mask-0.05: 2(-0.3,0) 3(-0.3,-0.5) 4(0.3,-0.5) 5(0.3,0) 6(0.3,0.5)
  body extent -0.5,-0.72 0.5,0.72, height 0.58
DSC0010J-MFG [mm]
  rrect42% 0.6x0.24 smd paste+0 mask+0: 1(-1.4,1) 2(-1.4,0.5) 3(-1.4,0) 4(-1.4,-0.5) 5(-1.4,-1) 6(1.4,-1) 7(1.4,-0.5) 8(1.4,0) 9(1.4,0.5) 10(1.4,1)
  round 0.225 smd paste-1000 mask+0: 11(-0.25,-1.45) 11(-0.25,1.448) 11(0.25,1.45) 11(0.25,-1.448)
  rrect6% 1.65x2.4 smd paste-1000 mask+0: 11(0,0)
  Top Layer region: 0.375,-1.2 0.375,-1.65 0.371,-1.669 0.36,-1.685 0.344,-1.696 0.325,-1.7 0.325,-1.7 0.175,-1.7 0.156,-1.696 0.14,-1.685 0.129,-1.669 0.125,-1.65 0.125,-1.65 0.125,-1.2
  Top Layer region: -0.125,-1.2 -0.125,-1.65 -0.132,-1.675 -0.15,-1.693 -0.175,-1.7 -0.175,-1.7 -0.325,-1.7 -0.344,-1.696 -0.36,-1.685 -0.371,-1.669 -0.375,-1.65 -0.375,-1.65 -0.375,-1.2
  Top Layer region: 0.125,1.2 0.125,1.65 0.129,1.669 0.14,1.685 0.156,1.696 0.175,1.7 0.175,1.7 0.325,1.7 0.344,1.696 0.36,1.685 0.371,1.669 0.375,1.65 0.375,1.65 0.375,1.2
  Top Layer region: -0.375,1.2 -0.375,1.65 -0.371,1.669 -0.36,1.685 -0.344,1.696 -0.325,1.7 -0.325,1.7 -0.175,1.7 -0.156,1.696 -0.14,1.685 -0.129,1.669 -0.125,1.65 -0.125,1.65 -0.125,1.2
  silkscreen extent -1.55,-1.55 1.55,2.16, body extent -1.8,-1.8 1.8,1.8, height 0.25
FCI_10118194-0001LF [mm] "USB-micro B USB 2.0, 0.65mm, 5 Pos, R/A, SMT"
  rrect25% 0.4x1.35 smd: 1(-1.3,4.125) 2(-0.65,4.125) 3(0,4.125) 4(0.65,4.125) 5(1.3,4.125)
  rrect100% 1.25x0.95 hole 0.55 slot 0.85 at 0 deg mask+0.064: 6(-2.5,4.15) 7(2.5,4.15)
  rrect50% 1.008x1.55 hole 0.5 slot 1.15 at 90 deg: 8(-3.5,1.45) 9(3.5,1.45)
  rrect7% 1.5x1.55 smd: 10(-1,1.45) 11(1,1.45)
  Top Layer region: -3.445,0.675 -3.544,0.675 -3.728,0.751 -3.869,0.892 -3.945,1.076 -3.945,1.175 -3.945,1.175 -3.945,1.175 -3.945,1.725 -3.945,1.824 -3.869,2.008 -3.728,2.149 -3.544,2.225 -3.445,2.225 -3.445,2.225 -2.3,2.225 -2.3,0.675
  Top Layer region: 3.445,0.675 3.544,0.675 3.728,0.751 3.869,0.892 3.945,1.076 3.945,1.175 3.945,1.175 3.945,1.175 3.945,1.725 3.945,1.824 3.869,2.008 3.728,2.149 3.544,2.225 3.445,2.225 3.445,2.225 2.3,2.225 2.3,0.675
  silkscreen extent -4,2.6 3.7,4.3, body extent -4.02,-1.23 4.03,4.35, height 2.72
Fiducial10-20 [mm]
  round 1 smd mask+0.5: 1(0,0)
  Top Layer keep-out circle w1.178: c0,0 r0.5
FP-CON-SMA-EDGE-S_CONN_JACK-MFG [mm]
  rrect8% 1.2x5 smd paste+0 mask+0: 1(0,-7.26)
  rrect6% 1.6x5 smd paste+0 mask+0: 2(-2.77,-7.26) 3(2.77,-7.26)
  rrect6% 1.6x5 smd far side paste+0 mask+0: 4(-2.77,-7.26) 5(2.77,-7.26)
  body extent -3.28,-9.86 3.28,4.86, height 0.25
IEC_HotSurface_Small [mil]
  silkscreen extent -107,-93 107,92
IND_LQG15H [mm] "MuRata"
  rect 0.55x0.6 smd: 1(-0.475,0) 2(0.475,0)
  silkscreen extent -1.3,-0.3 -0.95,0.3, body extent -0.52,-0.27 0.52,0.27, height 0.55
Johnson_142-0761-881 [mil] "Connector, TH, End launch SMA"
  rect 16x60 smd: 1(0,82.5)
  round 60 hole 45 mask+0: 2(-48,43.5) 3(-48,-43.5) 4(48,-43.5) 5(48,43.5)
  Top Layer region: -18.01,112.5 -160.01,112.5 -160.01,-105.5 -18.01,-105.5
  Top Layer region: 17.99,-105.49 159.99,-105.49 159.99,112.51 17.99,112.51
  silkscreen extent -172,-117 172,106, body extent -124,-67 123,497, height 128
Keystone5000 [mil] "For Keystone 500x miniature loop terminals"
  round 80 hole 40: 1(0,0)
  silkscreen extent -52,-52 52,52, body extent -49,-49 49,49, height 182
Keystone5001 [mil] "For Keystone 500x miniature loop terminals"
  round 80 hole 40: 1(0,0)
  silkscreen extent -52,-52 52,52, body extent -49,-49 49,49, height 182
Keystone5002 [mil] "For Keystone 500x miniature loop terminals"
  round 80 hole 40: 1(0,0)
  silkscreen extent -52,-52 52,52, body extent -49,-49 49,49, height 182
LED_LTST-C190 [mm] "Lite-On"
  rect 0.8x0.8 smd: 1(-0.75,0) 2(0.75,0)
  silkscreen extent -1.1,-0.8 1.89,0.8, body extent -0.85,-0.45 0.85,0.45, height 0.9
NGF0006A [mm] "TI"
  rect 0.6x0.25 smd: 1(-1.15,0.65) 2(-1.15,0) 3(-1.15,-0.65) 4(1.15,-0.65) 5(1.15,0) 6(1.15,0.65)
  rect 0.75x1.2 smd paste-0.38: 7(0,0)
  silkscreen extent -1.4,-1.25 1.4,1.25, body extent -1.3,-1.15 1.3,1.15, height 0.81
PN0080A_N [mm] "QFP, 80-Leads, Body 12x12mm, Pitch 0.5mm, IPC Medium Density"
  oval 1.45x0.3 smd: 1(-6.725,4.75) 2(-6.725,4.25) 3(-6.725,3.75) 4(-6.725,3.25) 5(-6.725,2.75) 6(-6.725,2.25) 7(-6.725,1.75) 8(-6.725,1.25) 9(-6.725,0.75) 10(-6.725,0.25) 11(-6.725,-0.25) 12(-6.725,-0.75) 13(-6.725,-1.25) 14(-6.725,-1.75) 15(-6.725,-2.25) 16(-6.725,-2.75) 17(-6.725,-3.25) 18(-6.725,-3.75) 19(-6.725,-4.25) 20(-6.725,-4.75) 41(6.725,-4.75) 42(6.725,-4.25) 43(6.725,-3.75) 44(6.725,-3.25) 45(6.725,-2.75) 46(6.725,-2.25) 47(6.725,-1.75) 48(6.725,-1.25) 49(6.725,-0.75) 50(6.725,-0.25) 51(6.725,0.25) 52(6.725,0.75) 53(6.725,1.25) 54(6.725,1.75) 55(6.725,2.25) 56(6.725,2.75) 57(6.725,3.25) 58(6.725,3.75) 59(6.725,4.25) 60(6.725,4.75)
  oval 0.3x1.45 smd: 21(-4.75,-6.725) 22(-4.25,-6.725) 23(-3.75,-6.725) 24(-3.25,-6.725) 25(-2.75,-6.725) 26(-2.25,-6.725) 27(-1.75,-6.725) 28(-1.25,-6.725) 29(-0.75,-6.725) 30(-0.25,-6.725) 31(0.25,-6.725) 32(0.75,-6.725) 33(1.25,-6.725) 34(1.75,-6.725) 35(2.25,-6.725) 36(2.75,-6.725) 37(3.25,-6.725) 38(3.75,-6.725) 39(4.25,-6.725) 40(4.75,-6.725) 61(4.75,6.725) 62(4.25,6.725) 63(3.75,6.725) 64(3.25,6.725) 65(2.75,6.725) 66(2.25,6.725) 67(1.75,6.725) 68(1.25,6.725) 69(0.75,6.725) 70(0.25,6.725) 71(-0.25,6.725) 72(-0.75,6.725) 73(-1.25,6.725) 74(-1.75,6.725) 75(-2.25,6.725) 76(-2.75,6.725) 77(-3.25,6.725) 78(-3.75,6.725) 79(-4.25,6.725) 80(-4.75,6.725)
  silkscreen extent -7.53,-5.6 5.6,6.92, body extent -7,-7 7,7, height 1.56
RHA0040C-MFG [mm]
  rrect40% 0.6x0.25 smd paste+0 mask+0: 1(-2.9,2.25) 2(-2.9,1.75) 3(-2.9,1.25) 4(-2.9,0.75) 5(-2.9,0.25) 6(-2.9,-0.25) 7(-2.9,-0.75) 8(-2.9,-1.25) 9(-2.9,-1.75) 10(-2.9,-2.25) 21(2.9,-2.25) 22(2.9,-1.75) 23(2.9,-1.25) 24(2.9,-0.75) 25(2.9,-0.25) 26(2.9,0.25) 27(2.9,0.75) 28(2.9,1.25) 29(2.9,1.75) 30(2.9,2.25)
  rrect40% 0.25x0.6 smd paste+0 mask+0: 11(-2.25,-2.9) 12(-1.75,-2.9) 13(-1.25,-2.9) 14(-0.75,-2.9) 15(-0.25,-2.9) 16(0.25,-2.9) 17(0.75,-2.9) 18(1.25,-2.9) 19(1.75,-2.9) 20(2.25,-2.9) 31(2.25,2.9) 32(1.75,2.9) 33(1.25,2.9) 34(0.75,2.9) 35(0.25,2.9) 36(-0.25,2.9) 37(-0.75,2.9) 38(-1.25,2.9) 39(-1.75,2.9) 40(-2.25,2.9)
  rrect2% 4.7x4.7 smd paste-1000 mask+0: 41(0,0)
  silkscreen extent -3.05,-3.05 3.05,3.05, body extent -3.3,-3.3 3.3,3.3, height 0.25
SNT-100-BK-G [mil] "Samtec STEP model"
  round 1 on Mech3: 0(0,0)
  body extent -100,-50 100,50, height 344
SOT-23 [mm] "SOT23, 3-Leads, Body 2.9x1.3mm, Pitch 0.95mm, Lead Span 2.5mm, IPC Medium Density"
  rrect50% 1x0.6 smd: 1(-1.2,0.95) 2(-1.2,-0.95) 3(1.2,0)
  silkscreen extent -1.62,-1.5 0.7,1.5, body extent -1.16,-1.45 1.21,1.45, height 1
SW_FSM4JSMA [mm] "Alcoswitch"
  rrect7% 1.4x2.1 smd: 1(2.25,4.55) 2(2.25,-4.55) 3(-2.25,4.55) 4(-2.25,-4.55)
  body extent -3,-5 3,5, height 5.09
TSW-103-07-G-S [mm] "Samtec 100mil, 1x3, 230 mil above insulator"
  rrect50% 1.65x1.65 hole 1.016: 1(-2.54,0)
  round 1.65 hole 1.016: 2(0,0) 3(2.54,0)
  body extent -3.81,-1.27 3.81,1.27, height 8.38

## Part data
C1 C2 C3 C8 C10 C12 C14 C16 C17 C18 C19 C20 C21 C23 C24 C25 C26 C27 C28 C29 C30 C31 C32 C33 C34 C57 C58 C65 C66: library part CMP-0076713-1, "CAP, CERM, 0.1 µF, 10 V,+/- 10%, X5R, 0201", Cap_Case=0201, Manufacturer="American Technical Ceramics", PartNumber=530Z104KT10T, Supplier Part Number 1=1284-1882-1-ND, TempCo=X5R, Tolerance_%=10%, Value2=10V, ValueDisplayed=0.1µF
C4 C51 C52 C53 C56 C61 C62 C68 C69 C70 C71: library part CMP-0086193-1, "CAP, CERM, 10 µF, 10 V,+/- 10%, X5R, 0603", Cap_Case=0603, Manufacturer=MuRata, TempCo=X5R, Tolerance_%=10%, Value2=10V, ValueDisplayed=10µF
C5: library part CMP-0009631-3, "CAP, CERM, 10nF, 6.3 V, +100/-0%, C0G/NP0, 0201", Cap_Case=0201, Manufacturer="AT Ceramics", Supplier Part Number 1=1284-1002-1-ND, TempCo=C0G/NP0, Tolerance_%=100%, Value1=Unknown, Value2=6.3V, ValueDisplayed=10nF
C6 C9 C11 C13 C15 C59 C60: library part CMP-0006608-2, "CAP, CERM, 1 µF, 25 V, +/- 10%, X5R, 0402", Cap_Case=0402, Manufacturer=MuRata, Supplier Part Number 1=490-10017-1-ND, TempCo=X5R, Tolerance_%=10%, Value1=Unknown, Value2=25V, ValueDisplayed=1µF
C7 C36 C42 C46 C47 C48 C54 C63 C67: library part CMP-0006829-4, "CAP, CERM, 0.1 uF, 16 V, +/- 10%, X7R, 0603", Cap_Case=0603, Manufacturer="Wurth Elektronik", Supplier Part Number 1=710-885012206046, TempCo=X7R, Tolerance_%=10%, Value1=Unknown, Value2=16V, ValueDisplayed=0.1uF
C35 C41 C43: library part CMP-0006831-4, "CAP, CERM, 1 uF, 16 V, +/- 10%, X7R, 0603", Cap_Case=0603, Manufacturer="Wurth Elektronik", Supplier Part Number 1=710-885012206052, TempCo=X7R, Tolerance_%=10%, Value1=Unknown, Value2=16V, ValueDisplayed=1uF
C37: library part CMP-0006825-5, "CAP, CERM, 2.2 uF, 16 V, +/- 20%, X5R, 0603", Cap_Case=0603, Manufacturer="Wurth Elektronik", Supplier Part Number 1=732-7915-1-ND, TempCo=X5R, Tolerance_%=20%, Value1=Unknown, Value2=16V, ValueDisplayed=2.2uF
C38: library part CMP-0077942-1, "CAP, CERM, 3300 pF, 50 V,+/- 10%, X7R, 0603", Cap_Case=0603, Manufacturer="Wurth Elektronik", Supplier Part Number 1=732-8004-1-ND, TempCo=X7R, Tolerance_%=10%, Value2=50V, ValueDisplayed=3300pF
C44: library part CMP-0006827-4, "CAP, CERM, 2200 pF, 16 V, +/- 10%, X7R, 0603", Cap_Case=0603, Manufacturer="Wurth Elektronik", Supplier Part Number 1=710-885012206036, TempCo=X7R, Tolerance_%=10%, Value1=Unknown, Value2=16V, ValueDisplayed=2200pF
C45 C50: library part CMP-0006893-4, "CAP, CERM, 220 pF, 50 V, +/- 5%, C0G/NP0, 0603", Cap_Case=0603, Manufacturer=Kemet, Supplier Part Number 1=399-1066-1-ND, TempCo=C0G/NP0, Tolerance_%=5%, Value1=Unknown, Value2=50V, ValueDisplayed=220pF
C49: library part CMP-0007398-4, "CAP, CERM, 0.47 uF, 16 V, +/- 10%, X7R, 0603", Cap_Case=0603, Manufacturer=MuRata, Supplier Part Number 1=490-3295-1-ND, TempCo=X7R, Tolerance_%=10%, Value1=Unknown, Value2=16V, ValueDisplayed=0.47uF
C55 C64: library part CMP-0064936-4, "CAP, CERM, 4.7 uF, 16 V,+/- 10%, X7R, 0603", Cap_Case=0603, Manufacturer=MuRata, TempCo=X7R, Tolerance_%=10%, Value1=Unknown, Value2=16V, ValueDisplayed=4.7uF
D1 D2: library part CMP-0002827-3, "LED, Green, SMD", Color=green, Manufacturer=Lite-On, PartNumber=LTST-C190GKT, Power_TotalModule=100mW, Value1=0.1W, Value2=2.1V
FID1 FID2 FID3 FID4 FID5 FID6: library part CMP-0077181-1, "Fiducial mark.  There is nothing to buy or mount.", Manufacturer=N/A
H1 H2 H3 H4: library part CMP-0079645-1, "BUMPER CYLIN 0.312\" DIA", Manufacturer=3M, Supplier Part Number 1=SJ61A6-ND
J1: library part CMP-0074596-2, "Receptacle, USB 2.0, Micro-USB Type B, R/A, SMT", Color=Black, Current_A=1.8A, Manufacturer=FCI, Supplier Part Number 1=609-4618-1-ND, Voltage_V=100V
J2 J3 J4 J5 J6 J7 J8 J9 J10 J11 J12 J13 J16 J18 J20 J21 J22 J24 J25 J26: library part CMP-0055835-1, "Connector, End launch SMA 50 ohm, TH", Manufacturer="Cinch Connectivity", PartNumber=142-0761-881, Supplier Part Number 1=J801-ND
J14 J15 J17 J19 J23: library part CMP-0088000-4, "CONN SMA JACK STR EDGE MNT", Manufacturer="RF Solutions Ltd.", PartNumber=CON-SMA-EDGE-S
J28 J29 J30: library part CMP-0075407-2, "Header, 100mil, 3x1, Gold, TH", Color=Black, Current_A=6.3A, Manufacturer=Samtec, Supplier Part Number 1=SAM1029-03-ND, Voltage_V=550V
L1 L2 L3 L4 L5 L9: library part CMP-0003352-2, "Ferrite Bead, 120 ohm @ 100 MHz, 3 A, 0603", Manufacturer=MuRata, PartNumber=BLM18SG121TN1D, Supplier Part Number 1=490-3996-1-ND, Value1="0.025 ohm", Value2=3A, ValueDisplayed="120 ohm"
L6 L7: library part CMP-0058614-1, "Inductor, Multilayer, Air Core, 18 nH, 0.3 A, 0.36 ohm, SMD", Manufacturer=MuRata, Supplier Part Number 1=490-2626-1-ND, Value1="0.36 ohm", Value2=0.3A, ValueDisplayed=18nH
Logo5: library part CMP-0074837-2, "IEC 61010-1 Hot Surface Warning", Manufacturer="Texas Instruments", PartNumber="CAUTION HOT SURFACE"
Q1: library part CMP-0000755-1, "MOSFET, N-CH, 50 V, 0.22 A, SOT-23", Alternate Manufacturer=None, Manufacturer="Fairchild Semiconductor", Supplier Part Number 1=BSS138CT-ND, Value2="1.7 nC"
R1 R17: library part CMP-0025785-4, "RES, 330, 5%, 0.1 W, AEC-Q200 Grade 0, 0603", Manufacturer=Vishay-Dale, Power_W=100mW, Supplier Part Number 1=541-330GCT-ND, TempCo="200 ppm/C", Tolerance_%=5%, Value2=0.1W, Value_Code=330R, ValueDisplayed=330
R2 R5 R8 R11: library part CMP-0026825-5, "RES, 10 k, 5%, 0.063 W, AEC-Q200 Grade 0, 0402", Manufacturer=Vishay-Dale, Power_W=63mW, Supplier Part Number 1=541-10KJCT-ND, TempCo="200 ppm/C", Tolerance_%=5%, Value2=0.063W, Value_Code=10k0, ValueDisplayed=10k
R3 R9: library part CMP-0026822-3, "RES, 0, 5%, 0.063 W, AEC-Q200 Grade 0, 0402", Manufacturer=Vishay-Dale, Power_W=63mW, Supplier Part Number 1=541-0.0JCT-ND, TempCo="200 ppm/C", Tolerance_%=5%, Value2=0.063W, Value_Code=0000, ValueDisplayed=0
R4 R6 R10 R20: library part CMP-0027008-4, "RES, 0, 5%, 0.05 W, 0201", Manufacturer=Vishay-Dale, Power_W=50mW, Supplier Part Number 1=72M6743, TempCo=ppm/C, Tolerance_%=5%, Value2=0.05W, Value_Code=0000, ValueDisplayed=0
R7: library part CMP-0026824-3, "RES, 100, 5%, 0.063 W, AEC-Q200 Grade 0, 0402", Manufacturer=Vishay-Dale, Power_W=63mW, Supplier Part Number 1=541-100JCT-ND, TempCo="200 ppm/C", Tolerance_%=5%, Value2=0.063W, Value_Code=100R, ValueDisplayed=100
R12 R13 R14 R16: library part CMP-0022201-5, "RES, 200, 1%, 0.1 W, AEC-Q200 Grade 0, 0603", Manufacturer=Vishay-Dale, Power_W=100mW, Supplier Part Number 1=541-200HCT-ND, TempCo="100 ppm/C", Tolerance_%=1%, Value2=0.1W, Value_Code=200R, ValueDisplayed=200
R15: library part CMP-0025736-4, "RES, 1.0 M, 5%, 0.1 W, AEC-Q200 Grade 0, 0603", Manufacturer=Vishay-Dale, Power_W=100mW, Supplier Part Number 1=541-1.0MGCT-ND, TempCo="200 ppm/C", Tolerance_%=5%, Value2=0.1W, Value_Code=1M00, ValueDisplayed=1.0M
R18: library part CMP-0025701-4, "RES, 10 k, 5%, 0.1 W, AEC-Q200 Grade 0, 0603", Manufacturer=Vishay-Dale, Power_W=100mW, Supplier Part Number 1=541-10KGCT-ND, TempCo="200 ppm/C", Tolerance_%=5%, Value2=0.1W, Value_Code=10k0, ValueDisplayed=10k
R19: library part CMP-0025786-4, "RES, 33 k, 5%, 0.1 W, AEC-Q200 Grade 0, 0603", Manufacturer=Vishay-Dale, Power_W=100mW, Supplier Part Number 1=541-33KGCT-ND, TempCo="200 ppm/C", Tolerance_%=5%, Value2=0.1W, Value_Code=33k0, ValueDisplayed=33k
R21 R22: library part CMP-0025787-4, "RES, 33, 5%, 0.1 W, AEC-Q200 Grade 0, 0603", Manufacturer=Vishay-Dale, Power_W=100mW, Supplier Part Number 1=541-33GCT-ND, TempCo="200 ppm/C", Tolerance_%=5%, Value2=0.1W, Value_Code=33R0, ValueDisplayed=33
R23: library part CMP-0025733-4, "RES, 1.5 k, 5%, 0.1 W, AEC-Q200 Grade 0, 0603", Manufacturer=Vishay-Dale, Power_W=100mW, Supplier Part Number 1=541-1.5KGCT-ND, TempCo="200 ppm/C", Tolerance_%=5%, Value2=0.1W, Value_Code=1k50, ValueDisplayed=1.5k
R24: library part CMP-0025697-4, "RES, 0, 5%, 0.1 W, AEC-Q200 Grade 0, 0603", Manufacturer=Vishay-Dale, Power_W=100mW, Supplier Part Number 1=541-0.0GCT-ND, TempCo="200 ppm/C", Tolerance_%=5%, Value2=0.1W, Value_Code=0000, ValueDisplayed=0
R25: library part CMP-0025738-4, "RES, 1.2 M, 5%, 0.1 W, AEC-Q200 Grade 0, 0603", Manufacturer=Vishay-Dale, Power_W=100mW, Supplier Part Number 1=541-1.2MGCT-ND, TempCo="200 ppm/C", Tolerance_%=5%, Value2=0.1W, Value_Code=1M20, ValueDisplayed=1.2M
R26 R41: library part CMP-0022038-4, "RES, 133 k, 1%, 0.1 W, AEC-Q200 Grade 0, 0603", Manufacturer=Vishay-Dale, Power_W=100mW, Supplier Part Number 1=541-133KHCT-ND, TempCo="100 ppm/C", Tolerance_%=1%, Value2=0.1W, Value_Code=133k
R27: library part CMP-0026095-2, "RES, 1.78 k, 1%, 0.063 W, AEC-Q200 Grade 0, 0402", Manufacturer=Vishay-Dale, Power_W=63mW, Supplier Part Number 1=541-1.78KLCT-ND, TempCo="100 ppm/C", Tolerance_%=1%, Value2=0.063W, Value_Code=1k78, ValueDisplayed=1.78k
R28 R43: library part CMP-0022031-4, "RES, 12.4 k, 1%, 0.1 W, AEC-Q200 Grade 0, 0603", Manufacturer=Vishay-Dale, Power_W=100mW, Supplier Part Number 1=541-12.4KHCT-ND, TempCo="100 ppm/C", Tolerance_%=1%, Value2=0.1W, Value_Code=12k4, ValueDisplayed=12.4k
R29 R31 R33 R35: library part CMP-0026404-2, "RES, 49.9, 1%, 0.063 W, AEC-Q200 Grade 0, 0402", Manufacturer=Vishay-Dale, Power_W=63mW, Supplier Part Number 1=541-49.9LCT-ND, TempCo="100 ppm/C", Tolerance_%=1%, Value2=0.063W, Value_Code=49R9, ValueDisplayed=49.9
R37: library part CMP-0026071-3, "RES, 1.00 k, 1%, 0.063 W, AEC-Q200 Grade 0, 0402", Manufacturer=Vishay-Dale, Power_W=63mW, Supplier Part Number 1=541-1.00KLCT-ND, TempCo="100 ppm/C", Tolerance_%=1%, Value2=0.063W, Value_Code=1k00, ValueDisplayed=1.00k
R40 R44: library part CMP-0022080-4, "RES, 16.5 k, 1%, 0.1 W, AEC-Q200 Grade 0, 0603", Manufacturer=Vishay-Dale, Power_W=100mW, Supplier Part Number 1=541-16.5KHCT-ND, TempCo="100 ppm/C", Tolerance_%=1%, Value2=0.1W, Value_Code=16k5, ValueDisplayed=16.5k
S1: library part CMP-0002134-3, "Switch, Tactile, SPST-NO, 0.05A, 12V, SMT", CurrentRating_mA=50A, Manufacturer="TE Connectivity", PartNumber=FSM4JSMA, Supplier Part Number 1=450-1129-ND
SH-J1 SH-J2 SH-J3: library part CMP-0003623-3, "Shunt, 100mil, Gold plated, Black", Alternate Manufacturer=3M, Alternate PartNumber=969102-0000-DA, Manufacturer=Samtec, Supplier Part Number 1=SAM8858-ND
TP1 TP4 TP5 TP6: library part CMP-0055139-2, "Test Point, Miniature, White, TH", Color=White, Manufacturer="Keystone Electronics", PartNumber=5002, Supplier Part Number 1=36-5002-ND
TP2 TP7 TP9: library part CMP-0055137-2, "Test Point, Miniature, Red, TH", Color=Red, Manufacturer="Keystone Electronics", PartNumber=5000, Supplier Part Number 1=36-5000-ND
TP3: library part CMP-0055138-2, "Test Point, Miniature, Black, TH", Color=Black, Manufacturer="Keystone Electronics", PartNumber=5001, Supplier Part Number 1=36-5001-ND
U1: library part CMP-0120269-1, "Low-Noise, High-Frequency JESD Buffer/Multiplier/Divider", Manufacturer="Texas Instruments", Max Frequency=12.8GHz, Max Supply Voltage=2.6V, Min Supply Voltage=2.4V, Nominal Supply Current=315-1100mA, Operating Temperature Range="-40°C to +85°C", PartNumber=LMX1205RHAT
U2: library part CMP-0038965-1, "25 MHz Mixed Signal Microcontroller with 128 KB Flash, 8192 B SRAM and 63 GPIOs, -40 to 85 degC, 80-pin QFP (PN), Green (RoHS & no Sb/Br)", Frequency(MHz)=25, Manufacturer="Texas Instruments", Temp Sensor=Yes
U3: library part CMP-0043120-3, "4-Channel ESD Solution for High-Speed Differential Interface, DRY0006A (USON-6)", Breakdown Voltage(Min)(V)=9, Differential Capacitance(pF)=0.05, IO Capacitance(Typ)(pF)=0.8, IO Leakage Current(nA)=Jan-00, Manufacturer="Texas Instruments", Operating Temperature Range="-40 to 85 C", Rating=Catalog
U4: library part CMP-0070655-2, "Ultra Low Noise, 150mA Linear Regulator for RF/Analog Circuits Requires No Bypass Capacitor, 6-pin LLP, Pb-Free", Manufacturer="Texas Instruments", PackageTopMarking=XTT*L16, PowerWise=N
U5 U6: library part CMP-0091022-1, "1-A, Ultra-Low Noise, Ultra-High PSRR, RF Voltage Regulator", Dropout Voltage=210mV, Manufacturer="Texas Instruments", Max Supply Voltage=5.5V, Min Supply Voltage=1.7V, Nominal Supply Current=15-47mA, Operating Temperature Range="-40°C to +150°C", Output Voltage=0.4-5.3V
U7: library part CMP-0051702-2, "Single Schmitt-Trigger Buffer, DBV0005A, LARGE T&R", F @ Nom Voltage(Max)(Mhz)=150, Generic Part Number=SN74LVC1G17, ICC @ Nom Voltage(Max)(mA)=0.01, Manufacturer="Texas Instruments", Operating Temperature Range(C)="-40 to 125,-40 to 85", Rating=Catalog, tpd @ Nom Voltage(Max)(ns)=11,6.5,5.5,5, Voltage(Nom)(V)=1.8,2.5,3.3,5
